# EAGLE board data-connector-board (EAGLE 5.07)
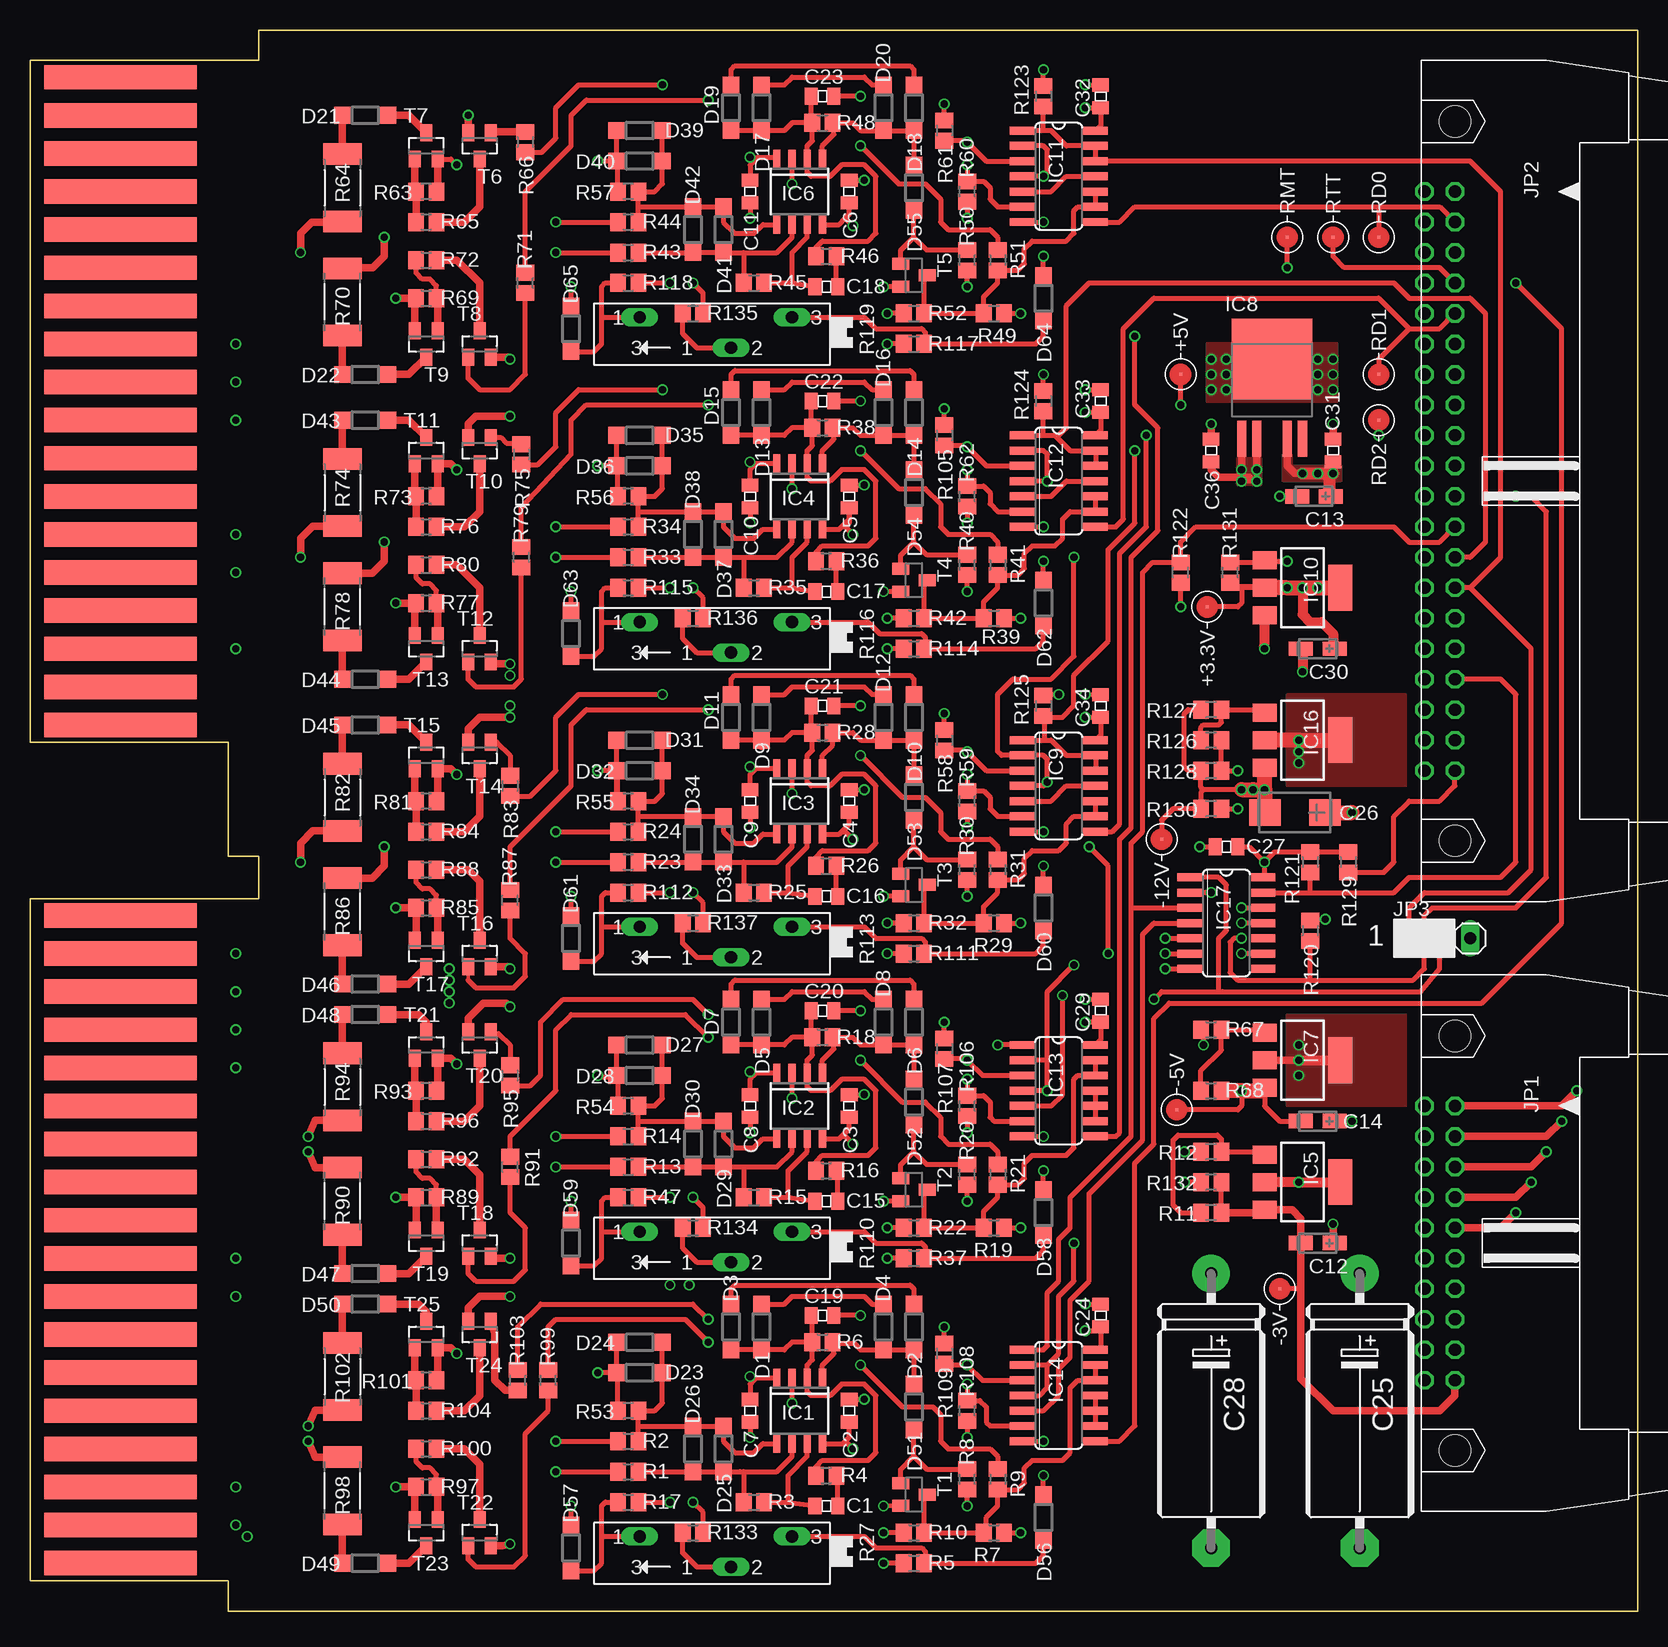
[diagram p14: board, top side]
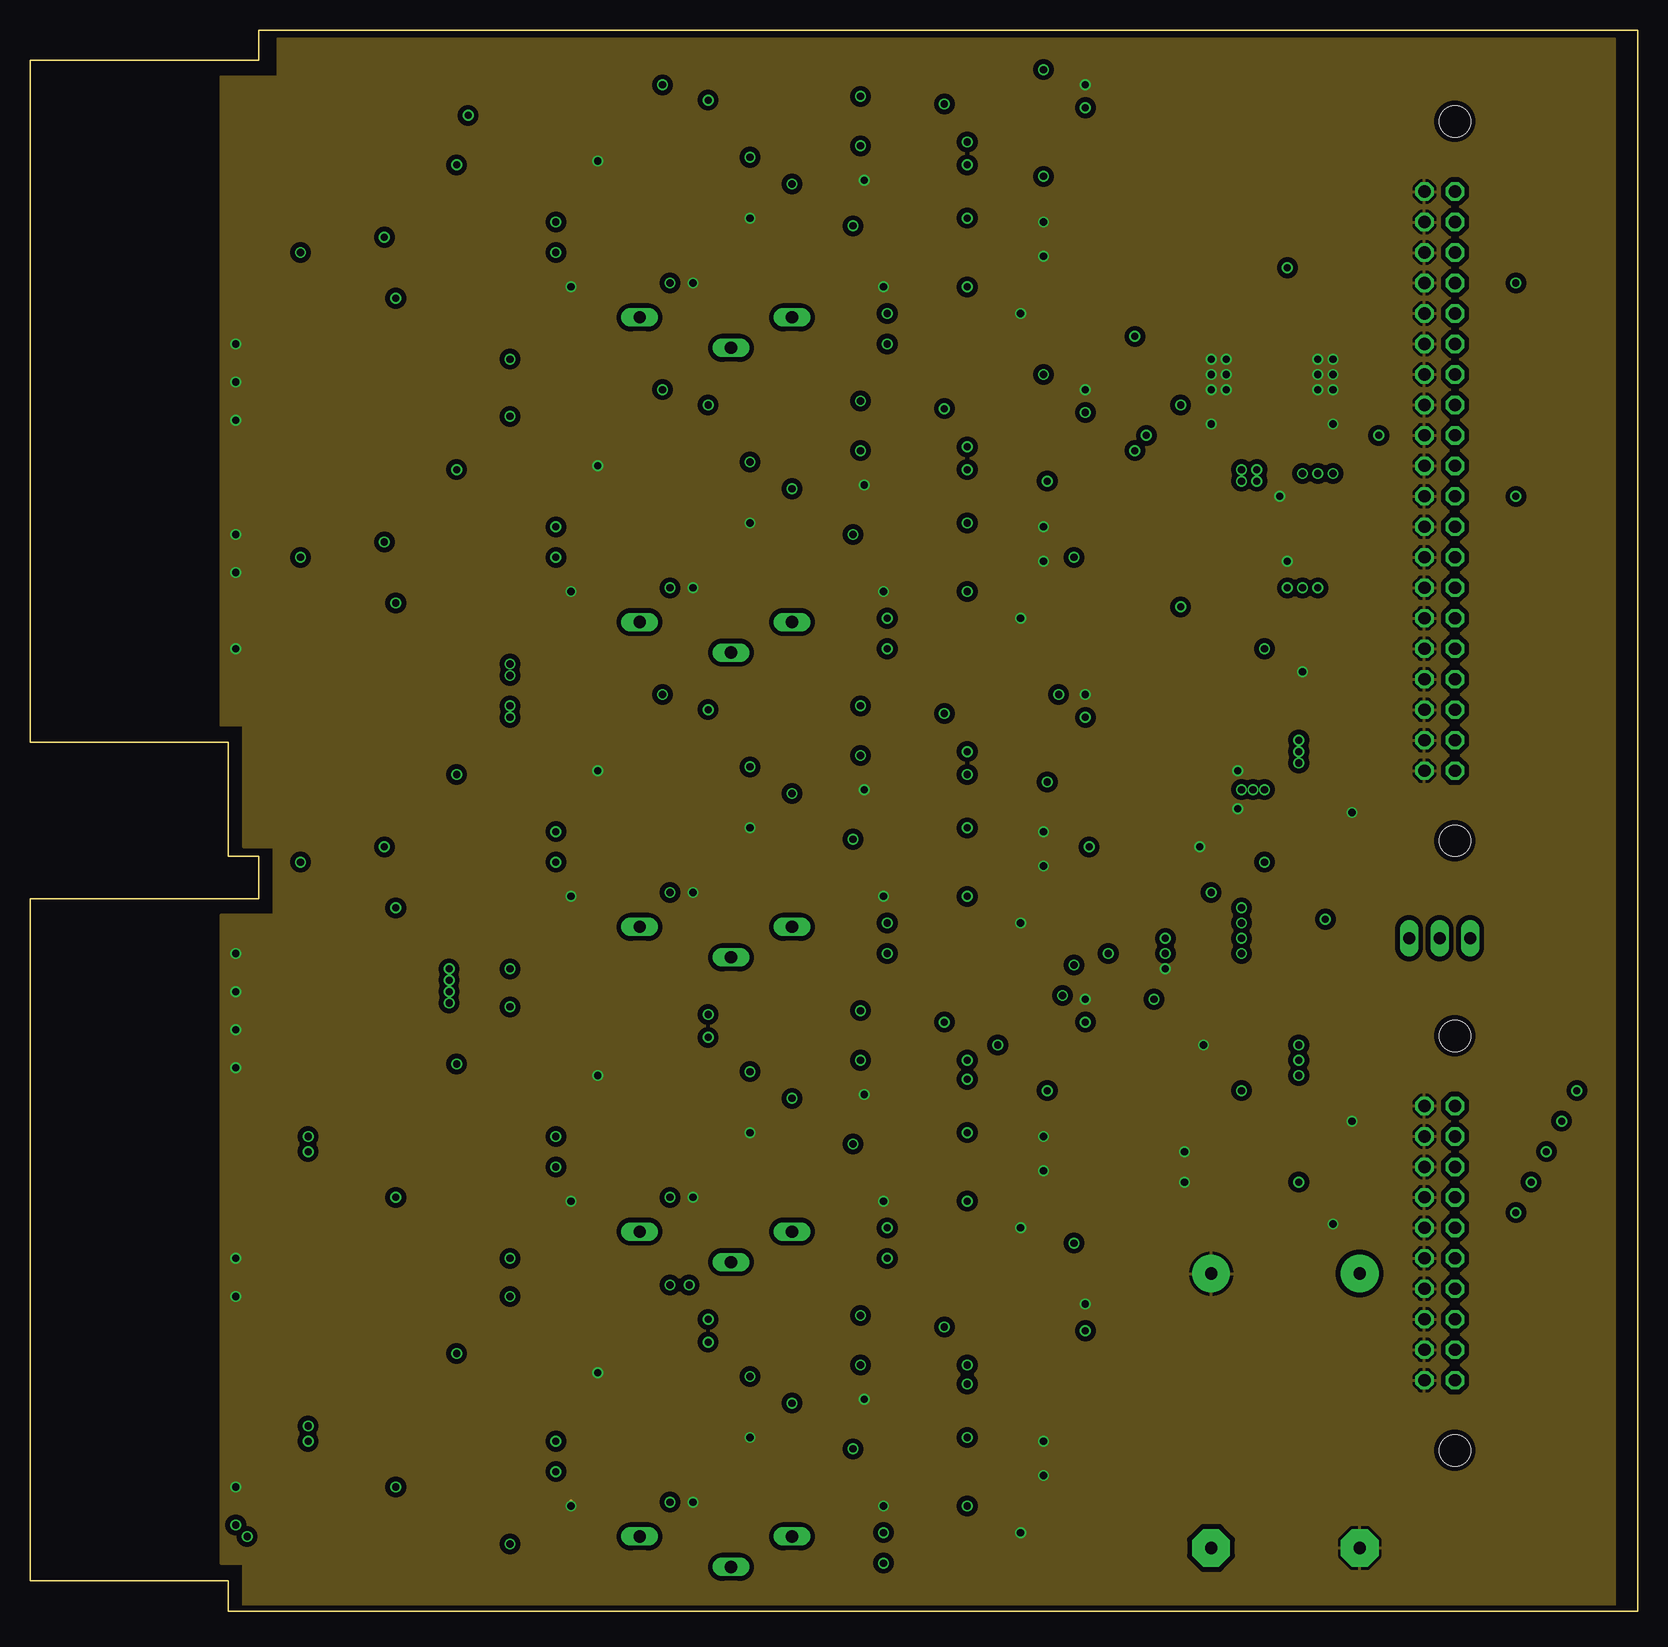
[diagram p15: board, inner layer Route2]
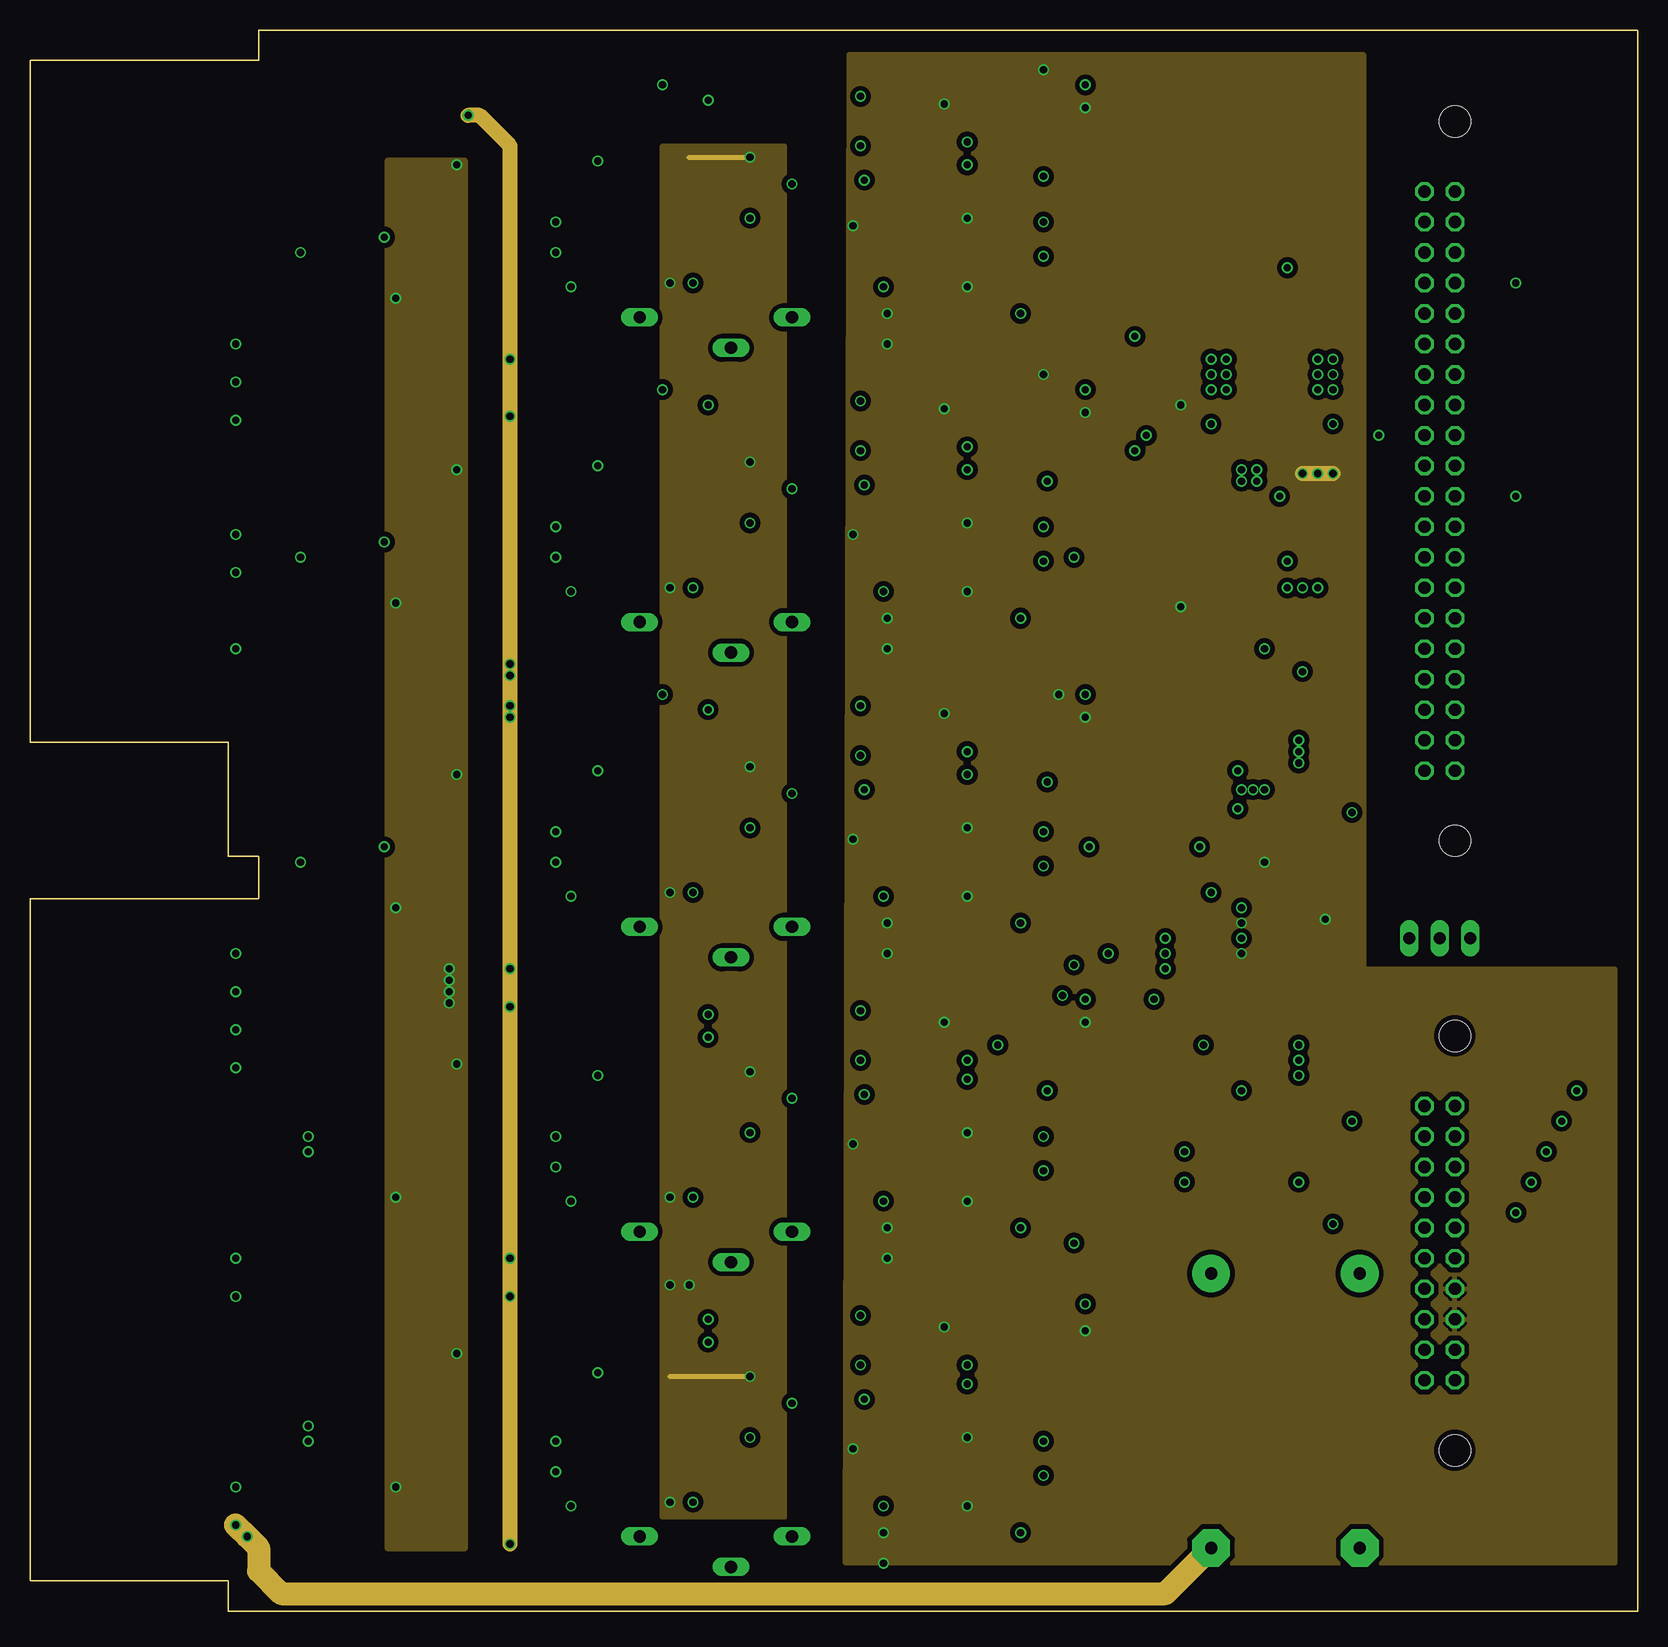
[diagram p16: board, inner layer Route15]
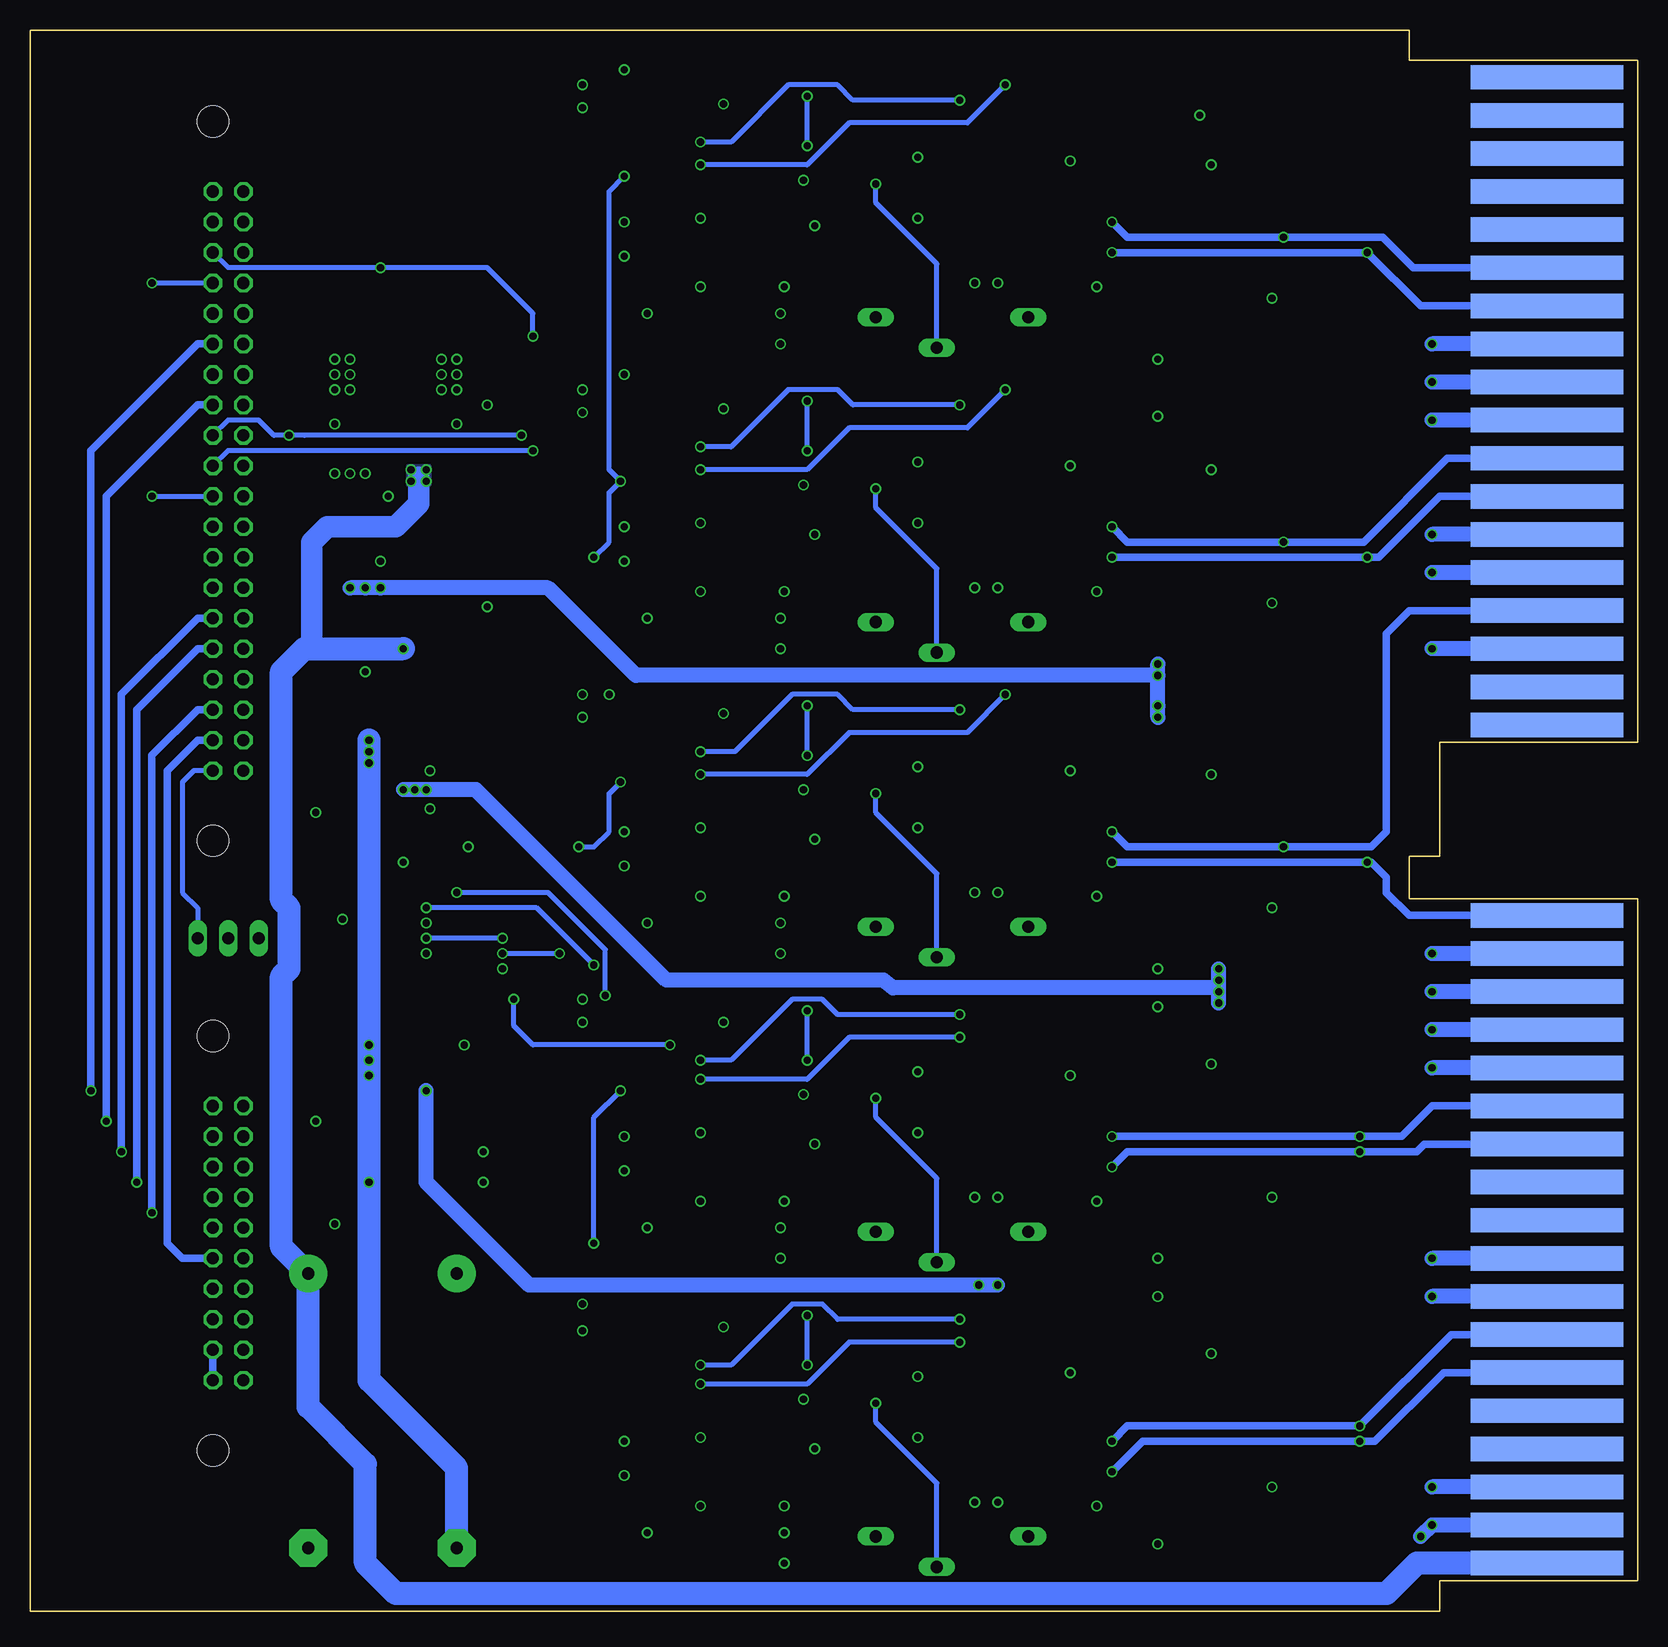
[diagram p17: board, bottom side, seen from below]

Size 133.99 x 131.76 mm. Coordinates in mm from the lower left corner, seen from the top.
Copper layers (1*2*15*16): Top 0.035mm / dielectric 0.2mm / Route2 0.0175mm / dielectric 0.3mm / Route15 0.0175mm / dielectric 0.2mm / Bottom 0.035mm
Design rules "SeeedStudio_4layer_DRU_no_angle_20140221": minimum track width 8mil, minimum drill 12mil, track to track 8mil, track to pad 8mil, pad to pad 8mil, via to via 8mil, smd to smd 0mil, copper to edge 10mil, drill to drill 8mil, minimum pad ring 6mil, minimum via ring 4mil, stop-mask expansion 4mil, vias tented up to drill 100mil, thermal gap 10mil

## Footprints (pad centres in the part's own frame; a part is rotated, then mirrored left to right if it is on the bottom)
0805 = smd 1.092 x 1.397: 1 -0.94,0; 2 0.94,0
CT3216 = smd 2 x 1.2: + -1.4,0; - 1.4,0
E22-9 = drill 1.016 pad 3.15 round: + -11.43,0 | drill 1.016 pad 3.15 octagon: - 11.43,0
CT6032 = smd 2.6 x 2.2: + -2.5,0; - 2.5,0
SOD123 = smd 1.4 x 1.4: A 1.9,0; C -1.9,0
SOIC8 = smd 0.6 x 1.5: 1 -1.905,-2.75; 2 -0.635,-2.75; 3 0.635,-2.75; 4 1.905,-2.75; 5 1.905,2.75; 6 0.635,2.75; 7 -0.635,2.75; 8 -1.905,2.75
SOT223@1 = smd 1.5 x 2: 1 -2.3,-3.15; 2 0,-3.15; 3 2.3,-3.15 | smd 3.8 x 2: 4 0,3.15
SOT223@2 = smd 1.5 x 2: 1 -2.3,-3.15; 2 0,-3.15; 3 2.3,-3.15 | smd 3.8 x 2: 4 0,3.15
PPAK = smd 0.76 x 3: 1 -2.54,-6.65; 2 -1.27,-6.65; 4 1.27,-6.65; 5 2.54,-6.65 | smd 6.7 x 6.7: TAB 0,0
SO14 = smd 0.66 x 2.032: 1 -3.81,-3.073; 2 -2.54,-3.073; 3 -1.27,-3.073; 4 0,-3.073; 5 1.27,-3.073; 6 2.54,-3.073; 7 3.81,-3.073; 8 3.81,3.073; 9 2.54,3.073; 10 1.27,3.073; 11 0,3.073; 12 -1.27,3.073; 13 -2.54,3.073; 14 -3.81,3.073
SOT223@3 = smd 1.5 x 2: 1 -2.3,-3.15; 2 0,-3.15; 3 2.3,-3.15 | smd 3.8 x 2: 4 0,3.15
SOT223 = smd 1.5 x 2: 1 -2.3,-3.15; 2 0,-3.15; 3 2.3,-3.15 | smd 3.8 x 2: 4 0,3.15
FLIPCHIP-2-OPEN = smd 12.7 x 2.032: AA1 6.921,0; AB1 6.921,3.175; AC1 6.921,6.35; AD1 6.921,9.525; AE1 6.921,12.7; AF1 6.921,15.875; AH1 6.921,19.05; AJ1 6.921,22.225; AK1 6.921,25.4; AL1 6.921,28.575; AM1 6.921,31.75; AN1 6.921,34.925; AP1 6.921,38.1; AR1 6.921,41.275; AS1 6.921,44.45; AT1 6.921,47.625; AU1 6.921,50.8; AV1 6.921,53.975; BA1 6.921,69.85; BB1 6.921,73.025; BC1 6.921,76.2; BD1 6.921,79.375; BE1 6.921,82.55; BF1 6.921,85.725; BH1 6.921,88.9; BJ1 6.921,92.075; BK1 6.921,95.25; BL1 6.921,98.425; BM1 6.921,101.6; BN1 6.921,104.775; BP1 6.921,107.95; BR1 6.921,111.125; BS1 6.921,114.3; BT1 6.921,117.475; BU1 6.921,120.65; BV1 6.921,123.825 | smd 12.7 x 2.032 bottom: AA2 6.921,0; AB2 6.921,3.175; AC2 6.921,6.35; AD2 6.921,9.525; AE2 6.921,12.7; AF2 6.921,15.875; AH2 6.921,19.05; AJ2 6.921,22.225; AK2 6.921,25.4; AL2 6.921,28.575; AM2 6.921,31.75; AN2 6.921,34.925; AP2 6.921,38.1; AR2 6.921,41.275; AS2 6.921,44.45; AT2 6.921,47.625; AU2 6.921,50.8; AV2 6.921,53.975; BA2 6.921,69.85; BB2 6.921,73.025; BC2 6.921,76.2; BD2 6.921,79.375; BE2 6.921,82.55; BF2 6.921,85.725; BH2 6.921,88.9; BJ2 6.921,92.075; BK2 6.921,95.25; BL2 6.921,98.425; BM2 6.921,101.6; BN2 6.921,104.775; BP2 6.921,107.95; BR2 6.921,111.125; BS2 6.921,114.3; BT2 6.921,117.475; BU2 6.921,120.65; BV2 6.921,123.825
TESTPOINT-2 = smd 0.254 x 0.254: P$1 0,0
2Z10/90-FRAMED = drill 1.016 octagon: 1 -11.43,-6.35; 2 -11.43,-3.81; 3 -8.89,-6.35; 4 -8.89,-3.81; 5 -6.35,-6.35; 6 -6.35,-3.81; 7 -3.81,-6.35; 8 -3.81,-3.81; 9 -1.27,-6.35; 10 -1.27,-3.81; 11 1.27,-6.35; 12 1.27,-3.81; 13 3.81,-6.35; 14 3.81,-3.81; 15 6.35,-6.35; 16 6.35,-3.81; 17 8.89,-6.35; 18 8.89,-3.81; 19 11.43,-6.35; 20 11.43,-3.81 | hole 2.6: 17.272,-3.81; -17.272,-3.81
2X20/90-FRAMED = drill 1.016 octagon: 1 -24.13,-6.35; 2 -24.13,-3.81; 3 -21.59,-6.35; 4 -21.59,-3.81; 5 -19.05,-6.35; 6 -19.05,-3.81; 7 -16.51,-6.35; 8 -16.51,-3.81; 9 -13.97,-6.35; 10 -13.97,-3.81; 11 -11.43,-6.35; 12 -11.43,-3.81; 13 -8.89,-6.35; 14 -8.89,-3.81; 15 -6.35,-6.35; 16 -6.35,-3.81; 17 -3.81,-6.35; 18 -3.81,-3.81; 19 -1.27,-6.35; 20 -1.27,-3.81; 21 1.27,-6.35; 22 1.27,-3.81; 23 3.81,-6.35; 24 3.81,-3.81; 25 6.35,-6.35; 26 6.35,-3.81; 27 8.89,-6.35; 28 8.89,-3.81; 29 11.43,-6.35; 30 11.43,-3.81; 31 13.97,-6.35; 32 13.97,-3.81; 33 16.51,-6.35; 34 16.51,-3.81; 35 19.05,-6.35; 36 19.05,-3.81; 37 21.59,-6.35; 38 21.59,-3.81; 39 24.13,-6.35; 40 24.13,-3.81 | hole 2.6: 29.972,-3.81; -29.972,-3.81
1X03 = drill 1.016 long: 1 -2.54,0; 2 0,0; 3 2.54,0
R0805 = smd 1.3 x 1.5: 1 -0.85,0; 2 0.85,0
SP19L = drill 1.016 long: A 5.715,-1.27; E -6.985,-1.27; S -1.905,1.27
R2512 = smd 1.8 x 3.2: 1 -2.8,0; 2 2.8,0
SOT23 = smd 1 x 1.4: 1 -0.95,-1.1; 2 0.95,-1.1; 3 0,1.1

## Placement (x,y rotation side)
C1  10n  [0805]  66.36,8.76 0 top
C2  100n  [0805]  68.26,16.7 270 top
C3  100n  [0805]  68.26,42.1 270 top
C4  100n  [0805]  68.26,67.5 270 top
C5  100n  [0805]  68.26,92.9 270 top
C6  100n  [0805]  68.26,118.3 270 top
C7  100n  [0805]  60.01,16.7 270 top
C8  100n  [0805]  60.01,42.1 270 top
C9  100n  [0805]  60.01,67.5 270 top
C10  100n  [0805]  60.01,92.9 270 top
C11  100n  [0805]  60.01,118.3 270 top
C12  10u/10V  [CT3216]  107.31,30.67 180 top
C13  10u/10V  [CT3216]  107,92.9 180 top
C14  10u/10V  [CT3216]  107.31,40.83 180 top
C15  10n  [0805]  66.36,34.16 0 top
C16  10n  [0805]  66.36,59.56 0 top
C17  10n  [0805]  66.36,84.96 0 top
C18  10n  [0805]  66.36,110.36 0 top
C19  10p  [0805]  66.04,24.64 0 top
C20  10p  [0805]  66.04,50.04 0 top
C21  10p  [0805]  66.04,75.44 0 top
C22  10p  [0805]  66.04,100.84 0 top
C23  10p  [0805]  66.04,126.24 0 top
C24  100n  [0805]  89.22,24.64 270 top
C25  330u  [E22-9]  110.81,16.7 270 top
C26  68u/16V  [CT6032]  105.41,66.55 180 top
C27  100n  [0805]  99.69,63.69 0 top
C28  330u  [E22-9]  98.42,16.7 270 top
C29  100n  [0805]  89.22,50.04 270 top
C30  10u/10V  [CT3216]  107.31,80.2 180 top
C31  2.2u  [0805]  108.58,96.71 90 top
C32  100n  [0805]  89.22,126.24 270 top
C33  100n  [0805]  89.22,100.84 270 top
C34  100n  [0805]  89.22,75.44 270 top
C36  2.2u  [0805]  98.42,96.71 270 top
D1  1N4148  [SOD123]  60.96,23.69 270 top
D2  1N4148  [SOD123]  73.66,23.69 270 top
D3  1N4148  [SOD123]  58.42,23.69 90 top
D4  1N4148  [SOD123]  71.12,23.69 90 top
D5  1N4148  [SOD123]  60.96,49.09 270 top
D6  1N4148  [SOD123]  73.66,49.09 270 top
D7  1N4148  [SOD123]  58.42,49.09 90 top
D8  1N4148  [SOD123]  71.12,49.09 90 top
D9  1N4148  [SOD123]  60.96,74.49 270 top
D10  1N4148  [SOD123]  73.66,74.49 270 top
D11  1N4148  [SOD123]  58.42,74.49 90 top
D12  1N4148  [SOD123]  71.12,74.49 90 top
D13  1N4148  [SOD123]  60.96,99.89 270 top
D14  1N4148  [SOD123]  73.66,99.89 270 top
D15  1N4148  [SOD123]  58.42,99.89 90 top
D16  1N4148  [SOD123]  71.12,99.89 90 top
D17  1N4148  [SOD123]  60.96,125.29 270 top
D18  1N4148  [SOD123]  73.66,125.29 270 top
D19  1N4148  [SOD123]  58.42,125.29 90 top
D20  1N4148  [SOD123]  71.12,125.29 90 top
D21  MBR0540T1  [SOD123]  27.94,124.65 180 top
D22  MBR0540T1  [SOD123]  27.94,103.06 180 top
D23  1N4148  [SOD123]  50.8,19.88 0 top
D24  1N4148  [SOD123]  50.8,22.42 180 top
D25  1N4148  [SOD123]  57.79,13.53 270 top
D26  1N4148  [SOD123]  55.25,13.53 90 top
D27  1N4148  [SOD123]  50.8,47.18 0 top
D28  1N4148  [SOD123]  50.8,44.64 180 top
D29  1N4148  [SOD123]  57.79,38.93 270 top
D30  1N4148  [SOD123]  55.25,38.93 90 top
D31  1N4148  [SOD123]  50.8,72.58 0 top
D32  1N4148  [SOD123]  50.8,70.04 180 top
D33  1N4148  [SOD123]  57.79,64.33 270 top
D34  1N4148  [SOD123]  55.25,64.33 90 top
D35  1N4148  [SOD123]  50.8,97.98 0 top
D36  1N4148  [SOD123]  50.8,95.44 180 top
D37  1N4148  [SOD123]  57.79,89.73 270 top
D38  1N4148  [SOD123]  55.25,89.73 90 top
D39  1N4148  [SOD123]  50.8,123.38 0 top
D40  1N4148  [SOD123]  50.8,120.84 180 top
D41  1N4148  [SOD123]  57.79,115.13 270 top
D42  1N4148  [SOD123]  55.25,115.13 90 top
D43  MBR0540T1  [SOD123]  27.94,99.25 180 top
D44  MBR0540T1  [SOD123]  27.94,77.66 180 top
D45  MBR0540T1  [SOD123]  27.94,73.85 180 top
D46  MBR0540T1  [SOD123]  27.94,52.26 180 top
D47  MBR0540T1  [SOD123]  27.94,28.13 180 top
D48  MBR0540T1  [SOD123]  27.94,49.72 180 top
D49  MBR0540T1  [SOD123]  27.94,4 180 top
D50  MBR0540T1  [SOD123]  27.94,25.59 180 top
D51  1N4148  [SOD123]  73.66,17.02 270 top
D52  1N4148  [SOD123]  73.66,42.42 270 top
D53  1N4148  [SOD123]  73.66,67.82 270 top
D54  1N4148  [SOD123]  73.66,93.22 270 top
D55  1N4148  [SOD123]  73.66,118.62 270 top
D56  1N4148  [SOD123]  84.45,7.81 270 top
D57  1N4148  [SOD123]  45.09,5.27 90 top
D58  1N4148  [SOD123]  84.45,33.21 270 top
D59  1N4148  [SOD123]  45.09,30.67 90 top
D60  1N4148  [SOD123]  84.45,58.61 270 top
D61  1N4148  [SOD123]  45.09,56.07 90 top
D62  1N4148  [SOD123]  84.45,84.01 270 top
D63  1N4148  [SOD123]  45.09,81.47 90 top
D64  1N4148  [SOD123]  84.45,109.41 270 top
D65  1N4148  [SOD123]  45.09,106.87 90 top
IC1  OPA2134D  [SOIC8]  64.13,16.7 180 top
IC2  OPA2134D  [SOIC8]  64.13,42.1 180 top
IC3  OPA2134D  [SOIC8]  64.13,67.5 180 top
IC4  OPA2134D  [SOIC8]  64.13,92.9 180 top
IC5  LM337  [SOT223@1]  106.05,35.75 270 top
IC6  OPA2134D  [SOIC8]  64.13,118.3 180 top
IC7  LM337  [SOT223@2]  106.05,45.91 270 top
IC8  LDFM50PT-TR  [PPAK]  103.5,104.33 0 top
IC9  7400D  [SO14]  85.72,68.77 270 top
IC10  LM1117-3.3  [SOT223@3]  106.05,85.28 270 top
IC11  7400D  [SO14]  85.72,119.57 270 top
IC12  7400D  [SO14]  85.72,94.17 270 top
IC13  7400D  [SO14]  85.72,43.37 270 top
IC14  7400D  [SO14]  85.72,17.97 270 top
IC16  LM337  [SOT223]  106.05,72.58 270 top
IC17  7404D  [SO14]  99.69,57.34 270 top
J1  FLIPCHIP_2  [FLIPCHIP-2-OPEN]  0.64,4 0 top
J2  RTT  [TESTPOINT-2]  108.58,114.49 90 top
J3  RMT  [TESTPOINT-2]  104.77,114.49 90 top
J4  RD0  [TESTPOINT-2]  112.39,114.49 90 top
J5  RD1  [TESTPOINT-2]  112.39,103.06 90 top
J6  RD2  [TESTPOINT-2]  112.39,99.25 270 top
J7  +5V  [TESTPOINT-2]  95.88,103.06 90 top
J8  +3.3V  [TESTPOINT-2]  98.11,83.69 270 top
J9  -3V  [TESTPOINT-2]  104.14,26.86 270 top
J10  -5V  [TESTPOINT-2]  95.57,41.78 90 top
J11  -12V  [TESTPOINT-2]  94.3,64.33 270 top
JP1  [2Z10/90-FRAMED]  122.55,30.67 270 top
JP2  [2X20/90-FRAMED]  122.55,94.17 270 top
JP3  [1X03]  117.47,56.07 0 top
R1  220  [R0805]  49.85,11.62 0 top
R2  220  [R0805]  49.85,14.16 0 top
R3  22k  [R0805]  60.33,9.08 0 top
R4  4k7  [R0805]  66.36,11.3 0 top
R5  2k2  [R0805]  73.66,4 0 top
R6  470k  [R0805]  66.04,22.42 0 top
R7  3k3  [R0805]  80.33,6.54 0 top
R8  4k7  [R0805]  78.1,10.99 90 top
R9  470k  [R0805]  80.64,10.99 270 top
R10  1k  [R0805]  73.66,6.54 0 top
R11  240  [R0805]  98.42,33.21 180 top
R12  330  [R0805]  98.42,38.29 180 top
R13  220  [R0805]  49.85,37.02 0 top
R14  220  [R0805]  49.85,39.56 0 top
R15  22k  [R0805]  60.33,34.48 0 top
R16  4k7  [R0805]  66.36,36.7 0 top
R17  2k2  [R0805]  49.85,9.08 0 top
R18  470k  [R0805]  66.04,47.82 0 top
R19  3k3  [R0805]  80.33,31.94 0 top
R20  4k7  [R0805]  78.1,36.39 90 top
R21  470k  [R0805]  80.64,36.39 270 top
R22  1k  [R0805]  73.66,31.94 0 top
R23  220  [R0805]  49.85,62.42 0 top
R24  220  [R0805]  49.85,64.96 0 top
R25  22k  [R0805]  60.33,59.88 0 top
R26  4k7  [R0805]  66.36,62.1 0 top
R27  10k  [SP19L]  56.52,4.95 180 top
R28  470k  [R0805]  66.04,73.22 0 top
R29  3k3  [R0805]  80.33,57.34 0 top
R30  4k7  [R0805]  78.1,61.79 90 top
R31  470k  [R0805]  80.64,61.79 270 top
R32  1k  [R0805]  73.66,57.34 0 top
R33  220  [R0805]  49.85,87.82 0 top
R34  220  [R0805]  49.85,90.36 0 top
R35  22k  [R0805]  60.33,85.28 0 top
R36  4k7  [R0805]  66.36,87.5 0 top
R37  2k2  [R0805]  73.66,29.4 0 top
R38  470k  [R0805]  66.04,98.62 0 top
R39  3k3  [R0805]  80.33,82.74 0 top
R40  4k7  [R0805]  78.1,87.19 90 top
R41  470k  [R0805]  80.64,87.19 270 top
R42  1k  [R0805]  73.66,82.74 0 top
R43  220  [R0805]  49.85,113.22 0 top
R44  220  [R0805]  49.85,115.76 0 top
R45  22k  [R0805]  60.33,110.68 0 top
R46  4k7  [R0805]  66.36,112.9 0 top
R47  2k2  [R0805]  49.85,34.48 0 top
R48  470k  [R0805]  66.04,124.02 0 top
R49  3k3  [R0805]  80.33,108.14 0 top
R50  4k7  [R0805]  78.1,112.59 90 top
R51  470k  [R0805]  80.64,112.59 270 top
R52  1k  [R0805]  73.66,108.14 0 top
R53  22k  [R0805]  49.85,16.7 180 top
R54  22k  [R0805]  49.85,42.1 180 top
R55  22k  [R0805]  49.85,67.5 180 top
R56  22k  [R0805]  49.85,92.9 180 top
R57  22k  [R0805]  49.85,118.3 180 top
R58  1k  [R0805]  76.2,72.58 270 top
R59  1k  [R0805]  78.1,67.5 90 top
R60  1k  [R0805]  78.1,118.3 90 top
R61  1k  [R0805]  76.2,123.38 270 top
R62  1k  [R0805]  78.1,92.9 90 top
R63  150  [R0805]  33.02,118.3 180 top
R64  75 2W  [R2512]  26.04,118.62 270 top
R65  680  [R0805]  33.02,115.76 0 top
R66  6k8  [R0805]  41.27,122.43 270 top
R67  715  [R0805]  98.42,48.45 0 top
R68  240  [R0805]  98.42,43.37 0 top
R69  150  [R0805]  33.02,109.41 0 top
R70  75 2W  [R2512]  26.04,109.09 90 top
R71  6k8  [R0805]  41.27,110.68 90 top
R72  680  [R0805]  33.02,112.59 0 top
R73  150  [R0805]  33.02,92.9 180 top
R74  75 2W  [R2512]  26.04,93.22 270 top
R75  6k8  [R0805]  40.96,96.39 270 top
R76  680  [R0805]  33.02,90.36 0 top
R77  150  [R0805]  33.02,84.01 0 top
R78  75 2W  [R2512]  26.04,83.69 90 top
R79  6k8  [R0805]  40.96,87.82 90 top
R80  680  [R0805]  33.02,87.19 0 top
R81  150  [R0805]  33.02,67.5 180 top
R82  75 2W  [R2512]  26.04,67.82 270 top
R83  6k8  [R0805]  40.01,68.77 270 top
R84  680  [R0805]  33.02,64.96 0 top
R85  150  [R0805]  33.02,58.61 0 top
R86  75 2W  [R2512]  26.04,58.29 90 top
R87  6k8  [R0805]  40.01,59.25 90 top
R88  680  [R0805]  33.02,61.79 0 top
R89  150  [R0805]  33.02,34.48 0 top
R90  75 2W  [R2512]  26.04,34.16 90 top
R91  6k8  [R0805]  40.01,37.02 90 top
R92  680  [R0805]  33.02,37.66 0 top
R93  150  [R0805]  33.02,43.37 180 top
R94  75 2W  [R2512]  26.04,43.69 270 top
R95  6k8  [R0805]  40.01,44.64 270 top
R96  680  [R0805]  33.02,40.83 0 top
R97  150  [R0805]  33.02,10.35 0 top
R98  75 2W  [R2512]  26.04,10.03 90 top
R99  6k8  [R0805]  43.18,19.24 90 top
R100  680  [R0805]  33.02,13.53 0 top
R101  150  [R0805]  33.02,19.24 180 top
R102  75 2W  [R2512]  26.04,19.56 270 top
R103  6k8  [R0805]  40.64,19.24 90 top
R104  680  [R0805]  33.02,16.7 0 top
R105  1k  [R0805]  76.2,97.98 270 top
R106  1k  [R0805]  78.1,42.1 90 top
R107  1k  [R0805]  76.2,46.86 270 top
R108  1k  [R0805]  78.1,16.7 90 top
R109  1k  [R0805]  76.2,21.46 270 top
R110  10k  [SP19L]  56.52,30.35 180 top
R111  2k2  [R0805]  73.66,54.8 0 top
R112  2k2  [R0805]  49.85,59.88 0 top
R113  10k  [SP19L]  56.52,55.75 180 top
R114  2k2  [R0805]  73.66,80.2 0 top
R115  2k2  [R0805]  49.85,85.28 0 top
R116  10k  [SP19L]  56.52,81.15 180 top
R117  2k2  [R0805]  73.66,105.6 0 top
R118  2k2  [R0805]  49.85,110.68 0 top
R119  10k  [SP19L]  56.52,106.55 180 top
R120  470  [R0805]  106.68,56.71 270 top
R121  470  [R0805]  106.68,62.42 270 top
R122  470  [R0805]  95.88,86.55 90 top
R123  470  [R0805]  84.45,126.24 270 top
R124  470  [R0805]  84.45,100.84 270 top
R125  470  [R0805]  84.45,75.44 270 top
R126  2k05  [R0805]  98.42,72.58 180 top
R127  240  [R0805]  98.42,75.12 180 top
R128  1k8  [R0805]  98.42,70.04 180 top
R129  470  [R0805]  109.85,62.42 270 top
R130  1k8  [R0805]  98.42,66.87 180 top
R131  220  [R0805]  100.01,86.55 90 top
R132  220  [R0805]  98.42,35.75 180 top
R133  2k2  [R0805]  55.25,6.54 0 top
R134  2k2  [R0805]  55.25,31.94 0 top
R135  2k2  [R0805]  55.25,108.14 0 top
R136  2k2  [R0805]  55.25,82.74 0 top
R137  2k2  [R0805]  55.25,57.34 0 top
T1  BC847  [SOT23]  73.66,9.72 270 top
T2  BC847  [SOT23]  73.66,35.12 270 top
T3  BC847  [SOT23]  73.66,60.52 270 top
T4  BC847  [SOT23]  73.66,85.92 270 top
T5  BC847  [SOT23]  73.66,111.32 270 top
T6  BC857B  [SOT23]  37.47,122.11 180 top
T7  IRLML0100TR  [SOT23]  33.02,122.11 0 top
T8  BC857B  [SOT23]  37.47,105.6 0 top
T9  IRLML0100TR  [SOT23]  33.02,105.6 180 top
T10  BC857B  [SOT23]  37.47,96.71 180 top
T11  IRLML0100TR  [SOT23]  33.02,96.71 0 top
T12  BC857B  [SOT23]  37.47,80.2 0 top
T13  IRLML0100TR  [SOT23]  33.02,80.2 180 top
T14  BC857B  [SOT23]  37.47,71.31 180 top
T15  IRLML0100TR  [SOT23]  33.02,71.31 0 top
T16  BC857B  [SOT23]  37.47,54.8 0 top
T17  IRLML0100TR  [SOT23]  33.02,54.8 180 top
T18  BC857B  [SOT23]  37.47,30.67 0 top
T19  IRLML0100TR  [SOT23]  33.02,30.67 180 top
T20  BC857B  [SOT23]  37.47,47.18 180 top
T21  IRLML0100TR  [SOT23]  33.02,47.18 0 top
T22  BC857B  [SOT23]  37.47,6.54 0 top
T23  IRLML0100TR  [SOT23]  33.02,6.54 180 top
T24  BC857B  [SOT23]  37.47,23.05 180 top
T25  IRLML0100TR  [SOT23]  33.02,23.05 0 top

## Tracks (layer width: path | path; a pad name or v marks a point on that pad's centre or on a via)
+3.3V  (via drill 0.6)
  Top 0.406: R131.1 100.43,85.38 102.13,85.38 102.23,85.28 103.5,85.28 | J8.P$1 100.65,83.69 100.96,84.01 100.96,85.28 v104.77,85.28
  Top 0.61: T22.2 39.37,5.44 v40.01,5.59 | T24.2 36.52,25.28 37.47,26.23 v40.01,26.23 | T18.2 38.41,29.4 v40.01,29.4 | T20.2 36.52,49.41 37.78,50.67 39.69,50.67 v40.01,50.36 | T14.2 36.52,73.54 37.47,74.49 v40.01,74.49 | T16.2 40.01,53.7 v40.01,53.53 | T12.2 38.57,79.1 38.73,78.95 39.37,78.93 v40.01,78.93 | T10.2 36.52,98.94 37.15,99.57 v40.01,99.57 | T8.2 39.84,104.5 v40.01,104.33 | T6.2 v36.52,124.65 v36.51,124.65
  Top 0.813: C30.+ 108.58,80.2 108.58,81.47 107.63,82.42 106.68,82.42 106.05,83.06 v106.05,85.28
  Top 1.27: v106.05,85.28 IC10.4 | v106.05,85.28 v107.31,85.28 | IC10.2 103.5,85.28 v104.77,85.28 v106.05,85.28
  Route15 1.27: v40.01,5.59 v40.01,26.23 v40.01,29.4 v40.01,50.36 v40.01,53.53 v40.01,74.49 v40.01,75.44 v40.01,77.98 v40.01,78.93 v40.01,99.57 v40.01,104.33 40.01,122.11 37.47,124.65 v36.51,124.65
  Bottom 1.27: v107.31,85.28 v106.05,85.28 v104.77,85.28 90.8,85.28 83.5,77.98 v40.01,77.98 | v40.01,74.49 v40.01,75.44 v40.01,77.98 | v40.01,77.98 v40.01,78.93
+10V  (via drill 0.6)
  Top 0.254: v100.96,94.17 100.96,95.44
  Top 0.406: 100.96,95.44 v100.96,95.12 v100.96,94.17 v102.23,94.17 v102.23,95.12
  Top 0.61: 100.96,95.44 IC8.1 | v102.23,95.12 IC8.2 | C36.2 98.42,95.12 99.06,94.49 101.6,94.49
  Top 0.813: IC10.3 102.89,80.86 v102.87,80.2
  Bottom 0.254: v100.96,94.17 v100.96,95.12 | v100.96,94.17 100.96,95.44 | v102.23,94.17 v100.96,94.17
  Bottom 1.778: 110.49,80.2 110.49,89.09 109.22,90.36 103.5,90.36 101.6,92.27 101.6,94.49
  Bottom 1.93: J1.AA2 18.41,4 20.95,1.46 103.5,1.46 106.05,4 106.05,12.26 110.81,17.02 C25.+ 113.03,30.35 113.03,52.9 112.39,53.53 112.39,58.61 113.03,59.25 113.03,78.3 111.12,80.2 110.49,80.2 v102.87,80.2
  pour Top (no thermals): 100.65,96.08 102.55,96.08 102.55,93.85 100.65,93.85
  pour Bottom: 100.65,95.44 102.55,95.44 102.55,93.85 100.65,93.85
-3V
  Top 0.406: IC5.3 102.66,33.21 | R11.1 R132.1 | 105.91,26.86 J9.P$1
  Top 0.61: 102.66,33.21 R11.1 | JP1.20 118.74,17.97 117.47,16.7 108.58,16.7 105.91,19.37 105.91,26.86 C12.- 105.91,32.71 105.17,33.45 IC5.3
  Top 0.813: C12.- 106.05,30.44
  Bottom 0.61: JP1.20 JP1.18
-12V  (via drill 0.6)
  Top 0.305: 33.97,92.9 R73.1
  Top 0.406: R127.2 96.52,75.12 96.2,74.8 96.2,70.36 96.52,70.04 R128.2 97.57,68.67 97.79,68.45 | v100.96,68.45 97.79,68.45 | 97.79,68.45 97.57,68.24 R130.2 95.25,66.87 94.3,65.91 J11.P$1 | T7.2 35.07,121.01 v35.56,120.52 | R63.1 33.97,120.84
  Top 0.61: T13.2 32.07,83.91 R77.1 v30.48,84.01 | 33.66,92.58 33.97,92.9 T11.2 35.07,95.61 v35.56,95.12 | T19.2 32.17,31.77 R89.1 v30.48,34.48 | R93.1 33.97,43.47 T21.2 35.07,46.08 v35.56,45.59 | R101.1 33.97,19.34 T25.2 35.07,21.95 v35.56,21.46 | T7.2 33.97,118.72 R63.1 | R81.1 33.97,67.6 T15.2 35.07,70.21 v35.56,69.72 | T9.2 32.07,109.31 R69.1 v30.48,109.41 | T17.2 32.17,56 R85.1 v30.48,58.61 | T23.2 32.07,10.25 R97.1 v30.48,10.35
  Top 1.27: IC16.3 102.89,66.56 C26.- 102.91,68.41 v102.87,68.45 v101.92,68.45 v100.96,68.45
  Bottom 1.27: v102.87,68.45 v101.92,68.45 v100.96,68.45 96.84,68.45 80.96,52.58 62.87,52.58 62.07,51.94 34.93,51.94 v34.93,51.63 | v34.93,51.63 v34.93,52.58 v34.93,53.53 | v34.93,50.67 v34.93,51.63
  pour Route15 (isolate 0.406): 36.2,120.84 36.2,5.27 29.84,5.27 29.84,120.84
-15V  (via drill 0.6)
  Top 0.61: v105.73,45.91 IC7.2
  Top 0.813: IC5.4 v105.73,35.75 IC5.2 | v105.73,45.91 IC7.4
  Top 1.27: IC16.2 v105.73,72.58 IC16.4
  Route15 1.93: v17.14,7.18 v18.1,6.22 19.05,5.27 19.05,3.37 20.95,1.46 94.61,1.46 C28.-
  Bottom 1.27: J1.AB2 v17.14,7.18 v18.1,6.22
  Bottom 1.93: v105.73,72.58 v105.73,70.68 v105.73,45.91 v105.73,35.75 105.73,19.24 98.42,11.94 C28.-
  other vias: 105.73,71.63 105.73,47.18 105.73,44.64
  pour Top (no thermals): 104.77,76.39 114.62,76.39 114.62,68.77 104.77,68.77
  pour Top (no thermals): 104.77,42.1 104.77,49.72 114.62,49.72 114.62,42.1
CON_ALL_HALT_L  (via drill 0.6)
  Top 0.61: JP1.10 122.55,31.94 v123.82,33.21
  Bottom 0.61: v123.82,33.21 123.82,71.31 120.02,75.12 JP2.36
D0(0)  (via drill 0.6)
  Top 0.406: v43.82,115.76 R44.1
  Top 0.61: v29.53,114.49 29.53,112.9 28.57,111.95 26.09,111.95 R70.2
  Bottom 0.61: J1.BP2 18.73,111.95 21.27,114.49 v29.53,114.49 42.55,114.49 v43.82,115.76
D0(1)  (via drill 0.6)
  Top 0.406: v43.82,113.22 R43.1
  Top 0.61: v22.54,113.22 22.54,114.81 23.49,115.76 25.98,115.76 R64.2
  Bottom 0.61: J1.BN2 18.1,108.78 v22.54,113.22 v43.82,113.22
D1(0)  (via drill 0.6)
  Top 0.406: v43.82,90.36 R34.1
  Top 0.61: R78.2 28.52,86.49 29.53,87.5 v29.53,89.09
  Bottom 0.61: v43.82,90.36 42.55,89.09 v29.53,89.09 22.86,89.09 15.88,96.08 J1.BJ2
D1(1)  (via drill 0.6)
  Top 0.406: v43.82,87.82 R33.1
  Top 0.61: R74.2 23.55,90.42 22.54,89.41 v22.54,87.82
  Bottom 0.61: J1.BH2 16.51,92.9 21.59,87.82 v22.54,87.82 v43.82,87.82
D2(0)  (via drill 0.6)
  Top 0.406: v43.82,64.96 R24.1
  Top 0.61: R86.2 28.52,61.09 29.53,62.1 v29.53,63.69
  Bottom 0.61: v43.82,64.96 42.55,63.69 v29.53,63.69 22.22,63.69 20.95,64.96 20.95,81.47 19.05,83.38 J1.BD2
D2(1)  (via drill 0.6)
  Top 0.406: v43.82,62.42 R23.1
  Top 0.61: R82.2 23.55,65.02 22.54,64.01 v22.54,62.42
  Bottom 0.61: J1.AV2 19.05,57.98 20.95,59.88 20.95,61.15 22.22,62.42 v22.54,62.42 v43.82,62.42
DATA1
  Top 0.406: T5.3 74.51,111.07 R52.2 R49.1 79.48,109.51 80.64,110.68 R51.2 82.33,111.74 82.87,112.27 82.87,113.54 83.5,114.17 86.36,114.17 86.99,114.81 86.99,116.71 87.31,117.03 IC11.9 IC11.10
DATA2
  Top 0.406: T4.3 74.51,85.67 R42.2 R39.1 79.48,84.11 80.64,85.28 R41.2 82.33,86.34 82.87,86.87 82.87,88.14 83.5,88.77 85.41,88.77 86.04,89.41 86.04,91 86.68,91.63 IC12.9 IC12.10
DATA3
  Top 0.406: T3.3 74.51,60.27 R32.2 R29.1 79.48,58.71 80.64,59.88 R31.2 82.33,60.94 82.87,61.47 82.87,62.74 83.5,63.37 85.72,63.37 86.36,64.01 86.36,65.6 86.99,66.23 IC9.9 IC9.10
F/R(0)_H
  Bottom 0.61: JP1.12 121.28,29.4 122.55,30.67 122.55,70.04 120.02,72.58 JP2.38
GND  (via drill 0.6)
  Top 0.305: 49,95.44 D36.A | 49,120.84 D40.A | 49,44.54 D28.A
  Top 0.406: D23.C v47.31,19.88 | D23.C D24.A | R53.2 49,19.46 D23.C | T1.2 71.43,8.76 v71.12,8.76 | IC10.1 102.87,87.61 | R54.2 49,44.54 47.41,44.54 v47.31,44.64 | D28.A D27.C | R19.2 v82.55,31.94 | D31.C D32.A 48.9,67.6 R55.2 49,69.94 D32.A v47.31,70.04 | R29.2 v82.55,57.34 | T3.2 72.39,59.57 v71.12,59.56 | D35.C D36.A v47.31,95.44 | R56.2 49,95.44 | R39.2 v82.55,82.74 | T4.2 72.71,84.97 v71.12,84.96 | C14.+ v110.17,40.83 | D40.A D39.C | R57.2 49,120.84 v47.31,120.84 | R49.2 v82.55,108.14 | v71.12,110.36 T5.2 | R67.1 97.79,48.45 v97.79,47.18 | T2.2 72.39,34.17 v71.12,34.16 | C2.1 v69.53,17.65 | C7.2 v60.01,14.48 | D57.A v45.09,8.76 | R7.2 v82.55,6.54 | IC14.7 v84.45,14.16 | v87.95,25.59 C24.1 | D59.A v45.09,34.16 | C8.2 v60.01,39.88 | C3.1 69.52,43.04 v69.53,43.05 | IC13.7 v84.45,39.56 | D58.C v84.45,36.7 | C29.1 v87.95,50.99 | C9.2 v60.01,65.28 | D61.A v45.09,59.56 | D63.A v45.09,84.96 | v69.53,68.45 68.27,68.45 C4.1 | D60.C v84.45,62.1 | C34.1 v87.95,76.39 | IC9.7 v84.45,64.96 | C10.2 v60.01,90.68 | C5.1 69.52,93.84 v69.53,93.85 | D62.C v84.45,87.5 | IC12.7 v84.45,90.36 | C33.1 88.89,101.78 v87.95,101.79 | D65.A v45.09,110.36 | D64.C v84.45,112.9 | IC11.7 v84.45,115.76 | C6.1 69.52,119.24 v69.53,119.25 | C11.2 v60.01,116.08 | C32.1 88.89,127.18 v87.95,127.19 | D56.C v84.45,11.3 | v94.61,53.53 IC17.7 | C13.- v104.14,92.9 | v97.47,63.69 C27.1 | R126.1 R128.1 v100.65,70.04 | R130.1 v100.65,66.87 | R132.2 v96.2,35.75 | R12.2 v96.2,38.29 | R131.2 102.71,87.4 IC10.1 | v104.77,87.5 102.97,87.5 IC10.1 | R133.2 56.09,8.23 v55.25,9.08 | R134.2 56.09,33.63 v55.25,34.48 | R137.2 56.09,59.03 v55.25,59.88 | R136.2 56.09,84.43 v55.25,85.28 | R135.2 56.09,109.83 v55.25,110.68
  Top 0.61: C30.- 106.05,80.07 | v108.58,32.26 108.58,30.67 C12.+ | C36.1 v98.42,98.93 | C31.2 v108.58,98.93
  Top 0.813: 106.05,80.07 v106.05,78.3
  Top 1.27: C26.+ v110.17,66.55
  Route2 0.406: v45.09,8.76 45.09,9.08
  Bottom 0.406: J1.BK2 6.99,99.25
  Bottom 1.27: J1.BM2 v17.14,105.6 | J1.BK2 v17.14,99.25 | J1.BF2 v17.14,89.73 | J1.BE2 v17.14,86.55 | J1.BL2 v17.14,102.43 | J1.AU2 v17.14,54.8 | J1.AT2 v17.14,51.63 | J1.AS2 v17.14,48.45 | J1.AR2 v17.14,45.28 | J1.AK2 v17.14,29.4 | J1.AJ2 v17.14,26.23 | J1.AC2 v17.14,10.35 | J1.BC2 v17.14,80.2
  other vias: 107.31,104.33 107.31,103.06 107.31,101.79 98.42,101.79 99.69,101.79 98.42,103.06 99.69,103.06 98.42,104.33 99.69,104.33 108.58,104.33 108.58,103.06 108.58,101.79
  pour Route2 (isolate 0.406): 132.08,131 20.64,131 20.64,127.83 15.88,127.83 15.88,73.85 17.78,73.85 17.78,63.69 20.32,63.69 20.32,57.98 15.88,57.98 15.88,4 17.78,4 17.78,0.51 132.08,0.51
  pour Top (no thermals): 108.9,105.6 98.11,105.6 98.11,100.84 108.9,100.84
MARK
  Top 0.406: T2.3 74.51,34.87 R22.2 R19.1 79.48,33.31 80.64,34.48 R21.2 82.33,35.54 82.87,36.07 82.87,37.34 83.5,37.97 86.36,37.97 86.99,38.61 86.99,44.32 87.31,44.64 IC13.12 IC13.13
MT(0)  (via drill 0.6)
  Top 0.406: v43.82,37.02 R13.1
  Top 0.61: v23.18,38.29 23.75,36.96 R90.2
  Bottom 0.61: J1.AN2 17.78,38.93 18.41,38.29 v23.18,38.29 42.55,38.29 v43.82,37.02
MT(1)  (via drill 0.6)
  Top 0.406: v43.82,39.56 R14.1
  Top 0.61: R94.2 23.75,40.89 v23.18,39.56
  Bottom 0.61: J1.AP2 17.14,42.1 19.68,39.56 v23.18,39.56 v43.82,39.56
N$1
  Top 0.406: 59.48,11.62 R3.1 | 59.48,11.62 59.15,11.63 D25.A D26.C 51.66,11.63 R1.2 | 59.48,11.62 62.23,11.62 63.5,12.89 IC1.6
N$2
  Top 0.406: T10.1 39.22,97.81 39.69,97.35 40.86,97.35 R75.1
N$3
  Top 0.406: 63.18,9.08 63.18,11.3 64.77,12.89 IC1.7 | R3.2 63.18,9.08 | 63.18,9.08 C1.1
N$4
  Top 0.406: D1.C 62.86,25.59 63.5,26.23 69.53,26.23 70.17,25.59 D4.A
N$5
  Top 0.406: D3.C D1.A 62.87,21.78 63.5,22.42 R6.1 | R6.1 65.19,24.23 C19.1 | R4.1 65.51,12.04 66.04,12.57 69.85,12.57 70.48,13.21 70.48,17.97 69.53,18.92 67.63,18.92 66.67,17.97 65.09,17.97 64.77,18.29 IC1.2 64.77,20.51 65.19,20.93 R6.1
N$6
  Top 0.61: D43.A 26.04,95.71 R74.1
N$7
  Top 0.406: 66.99,22.31 66.99,21.46 66.04,20.51 IC1.1 | 66.99,22.31 R6.2 | 66.99,22.31 68.68,22.31 69.21,21.78 D4.C 71.75,21.78 | 71.75,21.78 D2.A D51.C | D4.C 71.75,21.79 71.75,21.78
N$8
  Top 0.406: T1.1 72.56,11.79 73.66,12.89 | 73.66,12.89 D51.A | R8.2 74.71,11.84 73.66,12.89
N$9  (via drill 0.6)
  Top 0.406: v69.21,24.64 C19.2 | v69.21,20.51 72.71,17.02 75.25,17.02 75.88,16.38 75.88,14.16 76.52,13.53 80.01,13.53 80.64,12.89 R9.1
  Bottom 0.406: v69.21,20.51 v69.21,24.64
N$10  (via drill 0.6)
  Top 0.406: v69.21,126.24 C23.2 | v69.21,122.11 72.39,118.94 74.61,118.94 75.88,117.67 75.88,115.76 76.52,115.13 80.01,115.13 80.64,114.49 R51.1
  Bottom 0.406: v69.21,122.11 v69.21,126.24
N$11
  Top 0.406: D3.A 58.42,26.86 58.74,27.18 73.34,27.18 73.66,26.86 D2.C
N$12
  Top 0.406: C1.2 67.3,11.21 R4.2
N$13
  Top 0.61: D43.C 31.58,99.25 T11.3
N$15
  Top 0.61: T10.3 37.47,91.63 36.2,90.36 R76.2
N$17
  Top 0.61: T11.1 32.07,93 R73.2 R76.1
N$18
  Top 0.406: T12.1 36.52,77.66 37.15,77.03 40.32,77.03 40.96,77.66 R79.1
N$20
  Top 0.61: R78.1 D44.A
N$21
  Top 0.61: D44.C 31.58,77.66 T13.3
N$22
  Top 0.61: T12.3 37.47,85.28 35.56,87.19 R80.2
N$23
  Top 0.406: R80.1 32.17,86.13 32.7,85.6 33.34,85.6 33.87,85.07 R77.2
  Top 0.61: T13.1 33.97,83.91 R77.2
N$24
  Top 0.406: IC5.1 102.66,38.29 R12.1 99.27,39.35 98.96,39.66 95.67,39.66 95.25,39.24 95.25,33.85 95.88,33.21 R11.2
N$25  (via drill 0.6)
  Top 0.406: 78.52,68.35 R59.2 | IC9.6 80.64,66.23 80.01,66.87 80.01,67.82 79.48,68.35 78.52,68.35 | v52.71,76.39 45.72,76.39 43.82,74.49 43.82,70.04 41.7,67.92 R83.2 | 78.52,68.35 78.1,68.77 v78.1,69.72
  Bottom 0.406: v52.71,76.39 55.88,73.22 65.72,73.22 69.21,69.72 v78.1,69.72
N$26
  Top 0.406: T14.1 38.91,72.41 40.01,71.31 R83.1
N$27
  Top 0.406: R15.2 63.18,34.48 | 63.18,34.48 C15.1 | IC2.7 64.77,38.29 63.18,36.7 63.18,34.48
N$28
  Top 0.406: D5.C 62.86,50.99 63.5,51.63 69.53,51.63 70.17,50.99 D8.A
N$29
  Top 0.406: D7.C D5.A 62.87,47.18 63.5,47.82 R18.1 | C20.1 65.1,47.91 R18.1 | R16.1 65.51,37.44 66.04,37.97 69.85,37.97 70.48,38.61 70.48,43.37 69.53,44.32 67.63,44.32 66.67,43.37 65.09,43.37 64.77,43.69 IC2.2 64.77,45.91 65.19,46.33 R18.1
N$30
  Top 0.406: D8.C D6.A | D6.A 73.66,45.91 | IC2.1 66.04,45.91 66.99,46.86 66.99,47.71 R18.2 68.58,47.82 69.21,47.18 D8.C | D6.A D52.C | D8.C
N$31
  Top 0.61: D45.A R82.1
N$32
  Top 0.406: T2.1 72.56,37.19 73.66,38.29 | 73.66,38.29 D52.A | R20.2 74.71,37.24 73.66,38.29
N$33  (via drill 0.6)
  Top 0.406: v63.5,17.34 IC1.3 | R133.1 54.4,4.85 55.56,3.68 R27.S
  Bottom 0.406: R27.S 58.42,10.67 63.5,15.75 v63.5,17.34
N$34  (via drill 0.6)
  Top 0.406: v69.21,100.84 C22.2 | v69.21,96.71 72.39,93.54 74.61,93.54 75.88,92.27 75.88,90.36 76.52,89.73 80.01,89.73 80.64,89.09 R41.1
  Bottom 0.406: v69.21,96.71 v69.21,100.84
N$35
  Top 0.406: C15.2 67.3,36.48 R16.2
N$36
  Top 0.61: D45.C 31.58,73.85 T15.3
N$38
  Top 0.406: D7.A 58.42,52.26 58.74,52.58 73.34,52.58 73.66,52.26 D6.C
N$39
  Top 0.61: R84.2 36.2,64.96 37.47,66.23 T14.3
N$40
  Top 0.406: R25.2 63.18,59.88 | 63.18,59.88 C16.1 | IC3.7 64.77,63.69 63.18,62.1 63.18,59.88
N$41
  Top 0.406: D9.C 62.86,76.39 63.5,77.03 69.53,77.03 70.17,76.39 D12.A
N$42
  Top 0.406: 60.33,72.59 D11.C | 60.33,72.59 D9.A 62.87,72.58 63.5,73.22 R28.1 | 60.33,72.59 60.96,71.95 | C21.1 65.1,73.31 R28.1 | R26.1 65.51,62.84 66.04,63.37 69.85,63.37 70.48,64.01 70.48,68.77 69.53,69.72 67.63,69.72 66.67,68.77 65.09,68.77 64.77,69.09 IC3.2 64.77,71.31 65.19,71.73 R28.1
N$43
  Top 0.406: D12.C D10.A D53.C | IC3.1 66.04,71.31 66.89,72.16 R28.2 68.58,73.22 69.21,72.58 D12.C | D12.C
N$44
  Top 0.61: T15.1 32.07,67.92 R81.2 R84.1
N$45
  Top 0.406: 73.66,63.69 D53.A | T3.1 72.56,62.59 73.66,63.69 | R30.2 74.71,62.64 73.66,63.69
N$47
  Top 0.406: D56.A 84.45,4.64 83.82,4 R5.2 74.61,4.42 74.61,4.95 74.3,5.27 70.48,5.27 69.53,6.22 R27.E
N$48
  Top 0.406: R26.2 67.21,59.97 C16.2
N$49  (via drill 0.6)
  Top 0.406: v63.5,42.74 IC2.3 | R134.1 54.4,30.25 55.56,29.08 R110.S
  Bottom 0.406: v63.5,42.74 63.5,41.15 58.42,36.07 R110.S
N$50
  Top 0.406: IC9.5 85.09,67.5 86.36,68.77 IC9.11
N$51
  Top 0.406: D11.A 58.42,77.66 58.74,77.98 73.34,77.98 73.66,77.66 D10.C
N$52
  Top 0.305: 36.52,52.58 T16.1
  Top 0.406: 36.52,52.58 37.15,51.94 40.32,51.94 41.27,52.9 41.27,54.8 40.01,56.07 R87.1
N$53
  Top 0.406: R35.2 63.5,85.28 | 63.5,85.28 C17.1 | IC4.7 64.77,89.09 63.5,87.82 63.5,85.28
N$54
  Top 0.406: D13.C 62.86,101.79 63.5,102.43 69.53,102.43 70.17,101.79 D16.A
N$55
  Top 0.406: D15.C D13.A 62.87,97.99 63.5,98.62 R38.1 | R36.1 65.51,88.24 66.04,88.77 69.85,88.77 70.48,89.41 70.48,94.17 69.53,95.12 67.63,95.12 66.67,94.17 65.09,94.17 64.77,94.49 IC4.2 64.77,96.71 65.19,97.13 R38.1 | C22.1 65.1,98.71 R38.1
N$56
  Top 0.406: IC4.1 66.04,96.71 66.99,97.66 66.99,98.51 R38.2 68.58,98.62 69.21,97.99 D16.C D14.A D54.C
N$57
  Top 0.61: D46.A 26.04,55.81 R86.1
N$58
  Top 0.406: 73.66,89.09 D54.A | T4.1 72.56,87.99 73.66,89.09 | R40.2 74.71,88.04 73.66,89.09
N$60  (via drill 0.6)
  Top 0.406: R31.1 80.64,63.69 80.01,64.33 76.52,64.33 75.88,64.96 75.88,66.55 74.61,67.82 72.71,67.82 v69.21,71.31 | v69.21,75.44 C21.2
  Bottom 0.406: v69.21,71.31 v69.21,75.44
N$61
  Top 0.406: R36.2 67.21,85.19 C17.2
N$62
  Top 0.406: IC14.5 84.45,16.7 85.72,17.97 85.72,20.19 86.68,21.15 86.68,25.91 88.27,27.5 88.27,34.8 92.71,39.24 92.71,56.39 93.66,57.34 IC17.4
N$63  (via drill 0.6)
  Top 0.406: IC11.6 80.64,117.03 80.01,117.67 80.01,118.62 79.48,119.15 R60.2 v78.1,120.52 | v52.71,127.19 45.72,127.19 43.82,125.29 43.82,122.75 42.65,121.58 R66.2
  Bottom 0.406: v52.71,127.19 55.88,124.02 65.72,124.02 69.21,120.52 v78.1,120.52
N$64
  Top 0.406: D15.A 58.42,103.06 58.74,103.38 73.34,103.38 73.66,103.06 D14.C
N$65
  Top 0.61: D46.C 31.58,52.26 T17.3
N$66
  Top 0.406: R45.2 63.5,110.68 | 63.5,110.68 C18.1 | IC6.7 64.77,114.49 63.5,113.22 63.5,110.68
N$67
  Top 0.406: D17.C 62.86,127.19 63.5,127.83 69.53,127.83 70.17,127.19 D20.A
N$68
  Top 0.406: D19.C D17.A 62.87,123.39 63.5,124.02 R48.1 | C23.1 65.1,124.11 R48.1 | R46.1 65.51,113.64 66.04,114.17 69.85,114.17 70.48,114.81 70.48,119.57 69.53,120.52 67.63,120.52 66.67,119.57 65.09,119.57 64.77,119.89 IC6.2 64.77,122.11 65.19,122.53 R48.1
N$69
  Top 0.406: D20.C 69.21,123.38 68.58,124.02 R48.2 66.99,123.91 66.99,123.06 66.04,122.11 IC6.1 | D20.C D18.A D55.C | D20.C 71.75,123.38 | 71.75,123.38 73.02,123.38 | D20.C 71.75,123.39 71.75,123.38
N$70
  Top 0.61: R88.2 36.51,61.79 37.47,60.83 T16.3
N$71
  Top 0.406: T5.1 72.56,113.39 73.66,114.49 | 73.66,114.49 D55.A | R50.2 74.71,113.44 73.66,114.49
N$73
  Top 0.406: D57.C 47,3.37 47.62,4 47.62,6.22 | R17.1 47.94,9.08 47.62,8.76 47.62,6.54 47.62,6.22 | 47.62,6.22 R27.A
N$74
  Top 0.406: R46.2 67.21,110.91 C18.2
N$75  (via drill 0.6)
  Top 0.406: IC12.6 80.64,91.63 80.01,92.27 80.01,93.22 79.48,93.75 R62.2 v78.1,95.12 | v52.71,101.79 45.72,101.79 43.82,99.89 43.82,97.03 42.33,95.54 R75.2
  Bottom 0.406: v52.71,101.79 55.88,98.62 65.72,98.62 69.21,95.12 v78.1,95.12
N$76
  Top 0.406: IC13.11 IC13.10 IC13.9
N$77
  Top 0.406: D19.A 58.42,128.46 58.74,128.78 73.34,128.78 73.66,128.46 D18.C
N$78  (via drill 0.6)
  Top 0.406: IC13.6 80.33,40.83 80.01,41.15 80.01,42.42 79.48,42.95 R106.2 v78.1,44.32 | R91.2 40.01,39.56 43.82,43.37 43.82,48.45 45.09,49.72 54.61,49.72 v56.52,47.82
  Bottom 0.406: v78.1,44.32 69.21,44.32 65.72,47.82 v56.52,47.82
N$79  (via drill 0.6)
  Top 0.406: v63.5,118.94 IC6.3 | R135.1 54.4,106.45 55.56,105.28 R119.S
  Bottom 0.406: v63.5,118.94 63.5,117.35 58.42,112.27 R119.S
N$80  (via drill 0.6)
  Top 0.406: IC13.3 79.38,44.64 v78.1,45.91 78,46.01 R107.2 | R95.2 41.7,43.79 42.55,44.64 42.55,49.09 44.45,50.99 55.25,50.99 v56.52,49.72
  Bottom 0.406: v78.1,45.91 75.56,45.91 70.48,50.99 67.94,50.99 66.67,49.72 v56.52,49.72
N$81  (via drill 0.6)
  Top 0.406: R99.2 43.18,23.69 43.82,24.32 54.61,24.32 v56.52,22.42 | v78.1,18.92 R108.2 79.16,17.55 79.69,17.02 79.69,15.75 80.01,15.43 IC14.6
  Bottom 0.406: v56.52,22.42 65.72,22.42 69.21,18.92 v78.1,18.92
N$83  (via drill 0.6)
  Top 0.406: R109.2 76.3,20.51 v78.1,20.51 79.38,19.24 IC14.3 | R103.2 40.64,23.69 42.55,25.59 55.25,25.59 v56.52,24.32
  Bottom 0.406: v56.52,24.32 66.67,24.32 67.94,25.59 70.48,25.59 75.56,20.51 v78.1,20.51
N$84  (via drill 0.6)
  Top 0.406: v69.21,50.04 C20.2 | v69.21,45.91 72.71,42.42 74.61,42.42 75.88,41.15 75.88,39.56 76.52,38.93 80.01,38.93 80.64,38.29 R21.1
  Bottom 0.406: v69.21,45.91 v69.21,50.04
N$86
  Top 0.406: D58.A 84.45,30.04 83.82,29.4 R37.2 74.61,29.5 74.61,30.35 74.3,30.67 70.48,30.67 69.53,31.62 R110.E
N$87
  Top 0.406: D59.C 47,28.77 47.62,29.4 47.62,31.62 | R47.1 47.94,34.48 47.62,34.16 47.62,31.94 47.62,31.62 | 47.62,31.62 R110.A
N$88
  Top 0.406: D60.A 84.45,55.44 83.82,54.8 R111.2 74.61,54.9 74.61,55.75 74.3,56.07 70.48,56.07 69.53,57.02 R113.E
N$89
  Top 0.406: D61.C 47,54.17 47.62,54.8 47.62,57.02 | R112.1 47.94,59.88 47.62,59.56 47.62,57.34 47.62,57.02 | 47.62,57.02 R113.A
N$90
  Top 0.406: D62.A 84.45,80.84 83.82,80.2 R114.2 74.61,80.3 74.61,81.15 74.3,81.47 70.8,81.47 69.85,82.42 R116.E
N$91
  Top 0.406: D63.C 47,79.57 47.62,80.2 47.62,82.42 | R115.1 47.94,85.28 47.62,84.96 47.62,82.74 47.62,82.42 | 47.62,82.42 R116.A
N$92
  Top 0.406: D64.A 84.45,106.24 83.82,105.6 R117.2 74.61,105.7 74.61,106.55 74.3,106.87 70.48,106.87 69.53,107.82 R119.E
N$93
  Top 0.406: D65.C 47,104.97 47.62,105.6 47.62,107.82 | R118.1 47.94,110.68 47.62,110.36 47.62,108.14 47.62,107.82 | 47.62,107.82 R119.A
N$94
  Top 0.61: T6.3 37.47,117.03 36.2,115.76 R65.2
N$95
  Top 0.61: R65.1 R63.2 32.07,118.72 T7.1
N$96
  Top 0.406: R68.1 97.57,45.06 99.27,46.76 R67.2 102.66,48.45 IC7.1
N$97
  Top 0.406: T8.1 36.52,102.74 37.47,101.79 40.01,101.79 41.27,103.06 R71.1
N$99
  Top 0.61: T6.1 38.41,123.28 R66.1
N$100
  Top 0.61: R70.1 D22.A
N$101
  Top 0.406: R88.1 32.17,60.73 32.7,60.2 33.34,60.2 33.87,59.67 R85.2
  Top 0.61: T17.1 33.97,58.51 R85.2
N$102
  Top 0.305: 26.04,121.11 R64.1
  Top 0.61: 26.04,121.11 D21.A
N$103
  Top 0.61: D21.C 31.58,124.65 T7.3
N$104
  Top 0.406: T18.1 36.52,28.13 37.15,27.5 40.32,27.5 41.27,28.45 41.27,31.94 40.01,33.21 R91.1
N$105
  Top 0.61: D47.A R90.1
N$107
  Top 0.61: D47.C 31.58,28.13 T19.3
N$108
  Top 0.61: T18.3 37.47,36.39 36.2,37.66 R92.2
N$109
  Top 0.406: R92.1 32.17,36.6 32.7,36.07 33.34,36.07 33.87,35.54 R89.2
  Top 0.61: T19.1 33.87,31.77 R89.2
N$110
  Top 0.406: R95.1 40.01,47.18 39.05,48.13 38.56,48.13 T20.1
N$111
  Top 0.61: R94.1 D48.A
N$112
  Top 0.61: T21.3 33.02,49.09 32.39,49.72 D48.C
N$113
  Top 0.61: R96.2 36.2,40.83 37.47,42.1 T20.3
N$114
  Top 0.61: T21.1 32.07,43.47 R93.2 R96.1
N$116
  Top 0.406: IC14.11 IC14.10 IC14.9
N$117
  Top 0.406: IC12.11 86.36,94.17 85.09,92.9 IC12.5
N$118  (via drill 0.6)
  Top 0.406: v63.5,93.54 IC4.3 | R136.1 54.4,81.05 55.56,79.88 R116.S
  Bottom 0.406: v63.5,93.54 63.5,91.95 58.42,86.87 R116.S
N$119
  Top 0.406: IC16.1 102.89,75.12 R127.1 99.27,74.07 99.06,73.85 97.79,73.85 97.57,73.64 R126.2
N$120  (via drill 0.6)
  Top 0.406: v98.42,59.88 IC17.2 | v86.04,51.31 86.04,43.05 85.09,42.1 IC13.5
  Bottom 0.406: v98.42,59.88 90.8,59.88 86.04,55.12 v86.04,51.31
N$121  (via drill 0.6)
  Top 0.406: v63.5,68.14 IC3.3 | R137.1 54.4,55.65 55.56,54.48 R113.S
  Bottom 0.406: v63.5,68.14 63.5,66.55 58.42,61.47 R113.S
N$125
  Top 0.61: D22.C 31.58,103.06 T9.3
N$126
  Top 0.61: T8.3 37.47,110.68 35.56,112.59 R72.2
N$127
  Top 0.406: R72.1 32.17,111.53 32.7,111 33.34,111 33.87,110.47 R69.2
  Top 0.61: T9.1 33.97,109.63 R69.2
N$128
  Top 0.406: D24.C D23.A 52.71,19.24 52.71,17.34 52.07,16.7 R53.1 50.7,15.43 | D25.C | D25.C D26.A 50.7,15.43 | R2.2 50.7,15.43 | D25.C 57.79,14.16 58.74,13.21 60.33,13.21 61.07,13.95 IC1.5
N$129
  Top 0.406: 59.48,37.03 D29.A D30.C R13.2 | 59.48,37.03 R15.1 | 59.48,37.03 62.23,37.03 63.5,38.29 IC2.6
N$130
  Top 0.406: D29.C D30.A 50.7,40.83 | D29.C | R14.2 50.7,40.83 | 50.7,40.83 R54.1 52.07,42.1 52.7,42.73 D28.C D27.A | D29.C 57.79,39.56 58.74,38.61 60.33,38.61 61.07,39.35 IC2.5
N$131
  Top 0.406: T22.1 36.52,4.32 37.15,3.68 40.32,3.68 41.27,4.64 41.27,14.8 43.18,16.7 R99.1
N$132
  Top 0.61: D49.A 26.04,7.55 R98.1
N$133
  Top 0.406: D33.A D34.C R23.2 | D33.A 62.23,62.43 62.55,62.74 63.18,63.37 63.5,63.69 IC3.6 | R25.1 59.48,62.43 D33.A
N$134
  Top 0.406: D33.C D34.A 50.7,66.23 | D33.C | R24.2 50.7,66.23 | 50.7,66.23 R55.1 52.07,67.5 52.7,68.13 D32.C D31.A | D33.C 57.79,64.96 58.74,64.01 60.33,64.01 61.07,64.75 IC3.5
N$135
  Top 0.61: D49.C 31.58,4 T23.3
N$136
  Top 0.61: T22.3 37.47,12.26 36.2,13.53 R100.2
N$137
  Top 0.406: R33.2 D38.C D37.A 59.48,87.82 | 59.48,87.82 62.23,87.82 63.5,89.09 IC4.6 | R35.1 59.48,87.82
N$138
  Top 0.406: D35.A D36.C 52.71,93.54 52.07,92.9 R56.1 50.7,91.63 | R34.2 50.7,91.63 | 50.7,91.63 D38.A D37.C 57.79,90.36 58.74,89.41 60.33,89.41 61.07,90.15 IC4.5
N$139
  Top 0.406: R100.1 32.17,12.47 32.7,11.94 33.34,11.94 33.87,11.41 R97.2
  Top 0.61: T23.1 33.97,10.25 R97.2
N$140
  Top 0.61: R103.1 39.59,18.39 38.73,19.24 38.73,23.2 T24.1
N$141
  Top 0.305: D42.C
  Top 0.406: R43.2 D42.C | D42.C D41.A 59.48,113.22 | 59.48,113.22 62.23,113.22 63.5,114.49 IC6.6 | 59.48,113.22 R45.1
N$142
  Top 0.305: 50.7,117.03
  Top 0.406: D39.A D40.C 52.7,118.93 52.07,118.3 R57.1 50.7,117.03 R44.2 | 50.7,117.03 D42.A D41.C 57.79,115.76 58.74,114.81 60.33,114.81 61.07,115.55 IC6.5
N$143
  Top 0.61: R102.1 D50.A
N$144
  Top 0.61: D50.C 32.39,25.59 33.02,24.96 T25.3
N$145
  Top 0.61: T24.3 37.47,17.97 36.2,16.7 R104.2
N$146
  Top 0.61: T25.1 32.07,18.71 R101.2 R104.1
RD0
  Top 0.406: IC11.8 90.8,115.76 92.07,117.03 112.39,117.03 | 112.39,117.03 J4.P$1 112.39,117.03 | JP2.4 117.47,117.03 112.39,117.03
RD1
  Top 0.406: IC12.8 90.49,90.36 91.12,91 91.12,106.87 93.66,109.41 112.39,109.41 114.93,106.87 | JP2.10 117.47,106.87 114.93,106.87 | 114.93,106.87 112.39,104.33 J5.P$1
RD2  (via drill 0.6)
  Top 0.406: v93.03,97.98 93.03,90.36 90.8,88.14 90.8,65.6 90.17,64.96 IC9.8 | v112.39,97.98 J6.P$1
  Bottom 0.406: JP2.18 117.47,99.25 114.93,99.25 113.66,97.98 v112.39,97.98 111.12,97.98 v93.03,97.98
RMT  (via drill 0.6)
  Top 0.406: IC13.8 90.49,39.56 90.8,39.88 90.8,64.33 91.76,65.28 91.76,87.82 93.98,90.04 93.98,98.62 92.07,100.52 v92.07,106.24 | v104.77,111.95 J3.P$1
  Bottom 0.406: v92.07,106.24 92.07,108.14 95.88,111.95 v104.77,111.95 117.47,111.95 JP2.6
RTT  (via drill 0.6)
  Top 0.406: IC14.8 90.8,14.16 92.07,15.43 92.07,37.34 93.66,38.93 93.66,49.4 94.93,50.67 120.97,50.67 127.64,57.34 127.64,106.87 v123.82,110.68 | J2.P$1 108.58,112.9 109.54,111.95 117.47,111.95 JP2.8
  Bottom 0.406: v123.82,110.68 JP2.8
S/G(0)_H  (via drill 0.6)
  Top 0.61: v126.36,38.29 125.09,37.02 JP1.6
  Bottom 0.61: JP2.30 120.02,82.74 126.36,76.39 v126.36,38.29
S_WMT(1)  (via drill 0.6)
  Top 0.406: JP3.2 117.47,53.53 115.89,51.63 99.38,51.63 99.06,51.63 | 99.06,51.63 99.06,56.07 99.69,56.71 99.69,60.52 99.06,61.15 IC17.1 | v93.66,50.99 94.3,51.63 99.06,51.63 | IC13.1 v80.64,47.18
  Bottom 0.406: v93.66,50.99 93.66,48.77 92.07,47.18 v80.64,47.18
SEL_ECHO  (via drill 0.6)
  Top 0.61: JP1.2 127.64,42.1 v128.91,43.37
  Bottom 0.61: JP2.12 120.02,105.6 128.91,96.71 v128.91,43.37
T/M_ENAB_H  (via drill 0.6)
  Top 0.406: 84.77,20.51 IC14.2 | 84.77,20.51 84.77,18.61 84.14,17.97 IC14.4 | 84.77,20.51 85.72,21.46 85.72,26.23 86.99,27.5 v86.99,30.67 | 84.77,45.91 IC13.2 | 84.77,45.91 v84.77,43.37 IC13.4 | 84.77,45.91 84.77,51.63 v86.99,53.85 | v100.96,58.61 IC17.12
  Bottom 0.406: v86.99,30.67 86.99,41.15 v84.77,43.37 | v86.99,53.85 91.76,58.61 v100.96,58.61
T/M_ENAB_L
  Top 0.406: JP2.34 122.55,77.66 123.82,76.39 123.82,62.42 122.55,61.15 114.93,61.15 113.66,59.88 106.68,59.88 | IC17.13 106.68,59.88 | 106.68,59.88 R121.2
TIMING
  Top 0.406: T1.3 74.51,9.47 R10.2 R7.1 79.69,6.76 79.69,7.81 80.64,8.76 R9.2 82.33,10.14 82.87,10.67 82.87,11.94 83.5,12.57 86.04,12.57 86.68,13.21 86.68,18.61 87.31,19.24 IC14.12 IC14.13
TT(0)  (via drill 0.6)
  Top 0.406: v43.82,11.62 R1.1
  Top 0.61: R98.2 23.75,12.83 v23.18,14.16
  Bottom 0.61: v43.82,11.62 41.27,14.16 v23.18,14.16 21.91,14.16 16.19,19.88 J1.AF2
TT(1)  (via drill 0.6)
  Top 0.406: v43.82,14.16 R2.1
  Top 0.61: R102.2 23.75,16.76 v23.18,15.43
  Bottom 0.61: J1.AH2 15.56,23.05 v23.18,15.43 42.55,15.43 v43.82,14.16
UNIT(1)_H  (via drill 0.6)
  Top 0.61: JP1.8 123.82,34.48 v125.09,35.75
  Bottom 0.61: v125.09,35.75 125.09,75.12 120.02,80.2 JP2.32
V+  (via drill 0.6)
  Top 0.406: R10.1 v71.12,6.54 | R22.1 v71.44,31.94 | R32.1 v71.44,57.34 | IC1.8 67.73,13.95 67.94,14.16 | 67.94,14.16 68.26,14.48 C2.2 | 67.94,14.16 v68.58,13.53 | v78.1,8.76 R8.1 | R108.1 v78.1,14.48 | 88.9,21.78 88.8,21.88 IC14.14 89.22,21.78 C24.2 88.89,23.37 v87.95,23.37 | R109.1 v76.2,23.69 | IC2.8 67.42,39.35 67.63,39.56 | C3.2 68.26,40.2 67.63,39.56 | 67.63,39.56 67.94,39.56 v68.58,38.93 | v78.1,34.16 R20.1 | R37.1 v71.44,29.4 | R107.1 v76.2,49.09 | R106.1 v78.1,39.88 | v87.95,49.09 87.96,49.1 C29.2 89.22,47.6 IC13.14 | IC3.8 67.42,64.75 67.63,64.96 | C4.2 68.26,65.6 67.63,64.96 | 67.63,64.96 67.94,64.96 v68.58,64.33 | v78.1,59.56 R30.1 | R111.1 v71.44,54.8 | IC9.14 89.22,73 C34.2 87.93,74.5 v87.95,74.49 | R59.1 v78.1,65.28 | R58.1 v76.2,74.8 | IC4.8 67.42,90.15 68.26,91 C5.2 68.26,90.68 67.94,90.36 v68.58,89.73 | v78.1,84.96 R40.1 | R42.1 v71.44,82.74 | R114.1 v71.44,80.2 | R62.1 v78.1,90.68 | R105.1 v76.2,100.2 | IC12.14 89.22,98.4 C33.2 87.96,99.9 v87.95,99.89 | R52.1 v71.44,108.14 | IC6.8 67.42,115.55 67.94,116.08 | C6.2 68.26,116.4 67.94,116.08 | 67.94,116.08 v68.58,115.44 | R117.1 v71.44,105.6 | v78.1,110.36 R50.1 | R61.1 v76.2,125.6 | R60.1 v78.1,116.08 | IC11.14 89.22,123.8 C32.2 89.2,125.29 v87.95,125.29 | R5.1 v71.12,4 | R123.1 v84.45,128.46 | v95.88,83.69 R122.1 | IC17.11 v100.96,57.34 | 102.23,54.8 IC17.9 v100.96,54.8 | R129.1 R121.1 103.72,63.27 v102.87,62.42 | C27.2 101.6,63.69 v102.87,62.42 | IC17.14 102.87,61.15 v102.87,62.42 | R124.1 v84.45,103.06 | v85.72,76.39 84.56,76.39 R125.1 | v107.95,57.66 106.78,57.66 R120.1 | v95.88,100.52 J7.P$1
  Top 0.61: v106.05,94.81 105.41,94.81 104.77,95.44 IC8.4 | 108.27,93.54 C13.+
  Top 0.813: 108.27,93.54 108.27,92.9 C13.+ | v106.05,94.81 108.27,94.81 108.58,95.12 C31.1
  Top 1.016: 108.27,94.81 108.27,93.54 | v106.05,94.81 v108.58,94.81
  Route15 1.27: v106.05,94.81 v108.58,94.81
  other vias: 107.31,94.81
  pour Route15 (isolate 0.406): 67.94,4 68.26,129.73 111.12,129.73 111.12,94.17 111.12,53.53 132.08,53.53 132.08,4
  pour Top (no thermals): 105.09,95.44 109.22,95.44 109.22,94.17 104.46,94.17 104.46,96.39 105.09,96.39
V-  (via drill 0.6)
  Top 0.406: 102.66,43.37 IC7.3 102.89,42.08 104.14,40.83 C14.- | IC1.4 60.54,19.45 60.33,19.24 | R17.2 v53.34,9.08 | C7.1 60.01,18.92 60.33,19.24 | v60.01,19.56 60.33,19.24 | R47.2 v53.34,34.48 | IC2.4 60.54,44.85 60.33,44.64 | C8.1 60.01,44.32 60.33,44.64 | 60.33,44.64 v60.01,44.96 | C9.1 60.01,69.72 60.33,70.04 | IC3.4 60.54,70.25 60.33,70.04 | 60.33,70.04 v60.01,70.36 | R112.2 v53.34,59.88 | R115.2 v53.34,85.28 | IC4.4 60.54,95.65 60.33,95.44 | C10.1 60.01,95.12 60.33,95.44 | 60.33,95.44 v60.01,95.76 | R118.2 v53.34,110.68 | 60.33,120.84 60.64,121.16 62.12,121.16 IC6.4 | C11.1 60.01,120.52 60.33,120.84 | v60.01,121.16 60.33,120.84 | J10.P$1 100.65,41.78 100.96,42.1 v100.96,43.37
  Top 1.27: R68.2 v100.96,43.37 102.66,43.37
  Route15 0.406: 53.34,19.56 v60.01,19.56 | 54.93,121.16 v60.01,121.16
  Bottom 1.27: v53.34,27.18 92.39,27.18 100.96,35.75 v100.96,43.37
  other vias: 54.93,27.18
  pour Route15 (isolate 0.406): 52.71,122.11 62.87,122.11 62.87,89.09 62.87,7.81 52.71,7.81
W_DATA1_P  (via drill 0.6)
  Top 0.406: R61.2 78,122.53 v78.1,122.43 79.69,120.84 IC11.3 | v56.52,125.92 46.36,125.92 45.09,124.65 45.09,122.11 41.27,118.3 R71.2
  Bottom 0.406: v56.52,125.92 65.41,125.92 66.67,127.19 70.8,127.19 75.56,122.43 v78.1,122.43
W_DATA2_P  (via drill 0.6)
  Top 0.406: R105.2 78,97.13 v78.1,97.03 79.69,95.44 IC12.3 | v56.52,100.52 46.36,100.52 45.09,99.25 45.09,96.39 40.96,91.95 R79.2
  Bottom 0.406: v56.52,100.52 65.41,100.52 66.67,101.79 70.8,101.79 75.56,97.03 v78.1,97.03
W_DATA3_P  (via drill 0.6)
  Top 0.406: R58.2 78,71.73 v78.1,71.63 79.69,70.04 IC9.3 | R87.2 40.01,63.69 45.09,68.77 45.09,73.85 46.36,75.12 v56.52,75.12
  Bottom 0.406: v56.52,75.12 65.41,75.12 66.67,76.39 70.48,76.39 75.25,71.63 v78.1,71.63
WD0(0)
  Top 0.406: IC11.11 86.36,119.57 85.09,118.3 IC11.5
WD0(1)
  Top 0.406: 120.02,85.28 125.09,80.2 125.09,78.93 125.09,61.79 123.19,59.88 116.2,59.88 114.93,58.61 JP3.1 | 84.45,123.38 IC11.1 | 84.45,123.38 85.09,123.38 86.36,122.11 IC11.13 IC11.12 120.02,120.84 122.55,118.3 122.55,87.82 120.02,85.28 | 84.45,123.38 R123.2 | 120.02,85.28 JP2.28
WD1(1)
  Top 0.406: IC12.12 IC12.13 86.68,96.71 85.57,97.82 | IC12.1 84.45,97.98 | 84.45,97.98 85.41,97.98 85.57,97.82 | 84.45,97.98 R124.2 | JP2.26 120.02,87.82 121.28,89.09 121.28,108.14 120.02,109.41 114.93,109.41 113.66,110.68 88.27,110.68 86.36,108.78 86.36,98.62 85.57,97.82
WD2(1)  (via drill 0.6)
  Top 0.406: v92.07,96.71 92.07,90.68 89.85,88.46 89.85,80.84 86.99,77.98 86.99,75.44 86.04,74.49 84.56,74.49 | IC9.12 IC9.13 86.36,71.31 85.09,72.58 84.45,72.58 | IC9.1 84.45,72.58 | 84.56,74.49 R125.2 | 84.56,74.49 84.56,72.68 84.45,72.58
  Bottom 0.406: v92.07,96.71 117.47,96.71 JP2.20
WD_ENAB  (via drill 0.6)
  Top 0.406: IC9.4 84.45,68.77 v84.77,69.09 84.77,70.99 84.45,71.31 IC9.2 80.96,71.31 80.64,71.63 80.64,76.39 81.91,77.66 85.09,77.66 86.99,79.57 v86.99,87.82 | IC12.4 v84.77,94.17 84.77,96.39 84.45,96.71 IC12.2 | IC11.2 84.45,122.11 84.77,121.79 84.77,119.89 v84.45,119.57 IC11.4 | v94.61,54.8 IC17.6 | v89.85,54.8 89.85,62.1 v88.27,63.69
  Bottom 0.406: v86.99,87.82 85.72,89.09 85.72,93.22 v84.77,94.17 85.72,95.12 85.72,118.3 v84.45,119.57 | v89.85,54.8 v94.61,54.8 | v88.27,63.69 86.99,63.69 85.72,64.96 85.72,68.14 v84.77,69.09
WD_ENAB_TD8E  (via drill 0.6)
  Top 0.406: v123.82,92.9 125.09,92.9 126.36,91.63 126.36,61.15 123.82,58.61 116.84,58.61 116.2,57.98 116.2,53.53 115.25,52.58 106.68,52.58 | v94.61,56.07 IC17.5 | v100.96,56.07 100.33,56.07 100.01,55.75 100.01,53.21 100.65,52.58 106.68,52.58 | 106.68,52.58 R120.2
  Bottom 0.406: v123.82,92.9 JP2.22 | v94.61,56.07 v100.96,56.07
WMT(1)
  Top 0.406: R129.2 112.81,61.57 113.66,62.42 113.66,66.23 114.93,67.5 117.47,67.5 118.74,68.77 JP2.40
  Bottom 0.406: JP3.3 120.02,58.61 121.28,59.88 121.28,69.09 120.33,70.04 JP2.40
WRT_ECHO  (via drill 0.6)
  Top 0.61: v127.64,40.83 126.36,39.56 JP1.4
  Bottom 0.61: JP2.16 120.02,100.52 127.64,92.9 v127.64,40.83
WTT(1)
  Top 0.406: IC14.1 84.45,21.78 84.77,22.1 84.77,26.54 85.72,27.5 85.72,30.99 86.68,31.94 86.68,34.48 91.76,39.56 91.76,58.61 | 91.76,58.61 91.76,64.01 92.71,64.96 92.71,86.55 93.56,87.4 R122.2 95.88,89.09 97.16,90.36 113.66,90.36 114.93,89.09 117.47,89.09 JP2.24 | 91.76,58.61 IC17.3

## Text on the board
tNames: 1
tDocu: 1-2 TD8E
bDocu: TD8E interface v1.1 Anders Sandahl 2020 | www.pdp-9.net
